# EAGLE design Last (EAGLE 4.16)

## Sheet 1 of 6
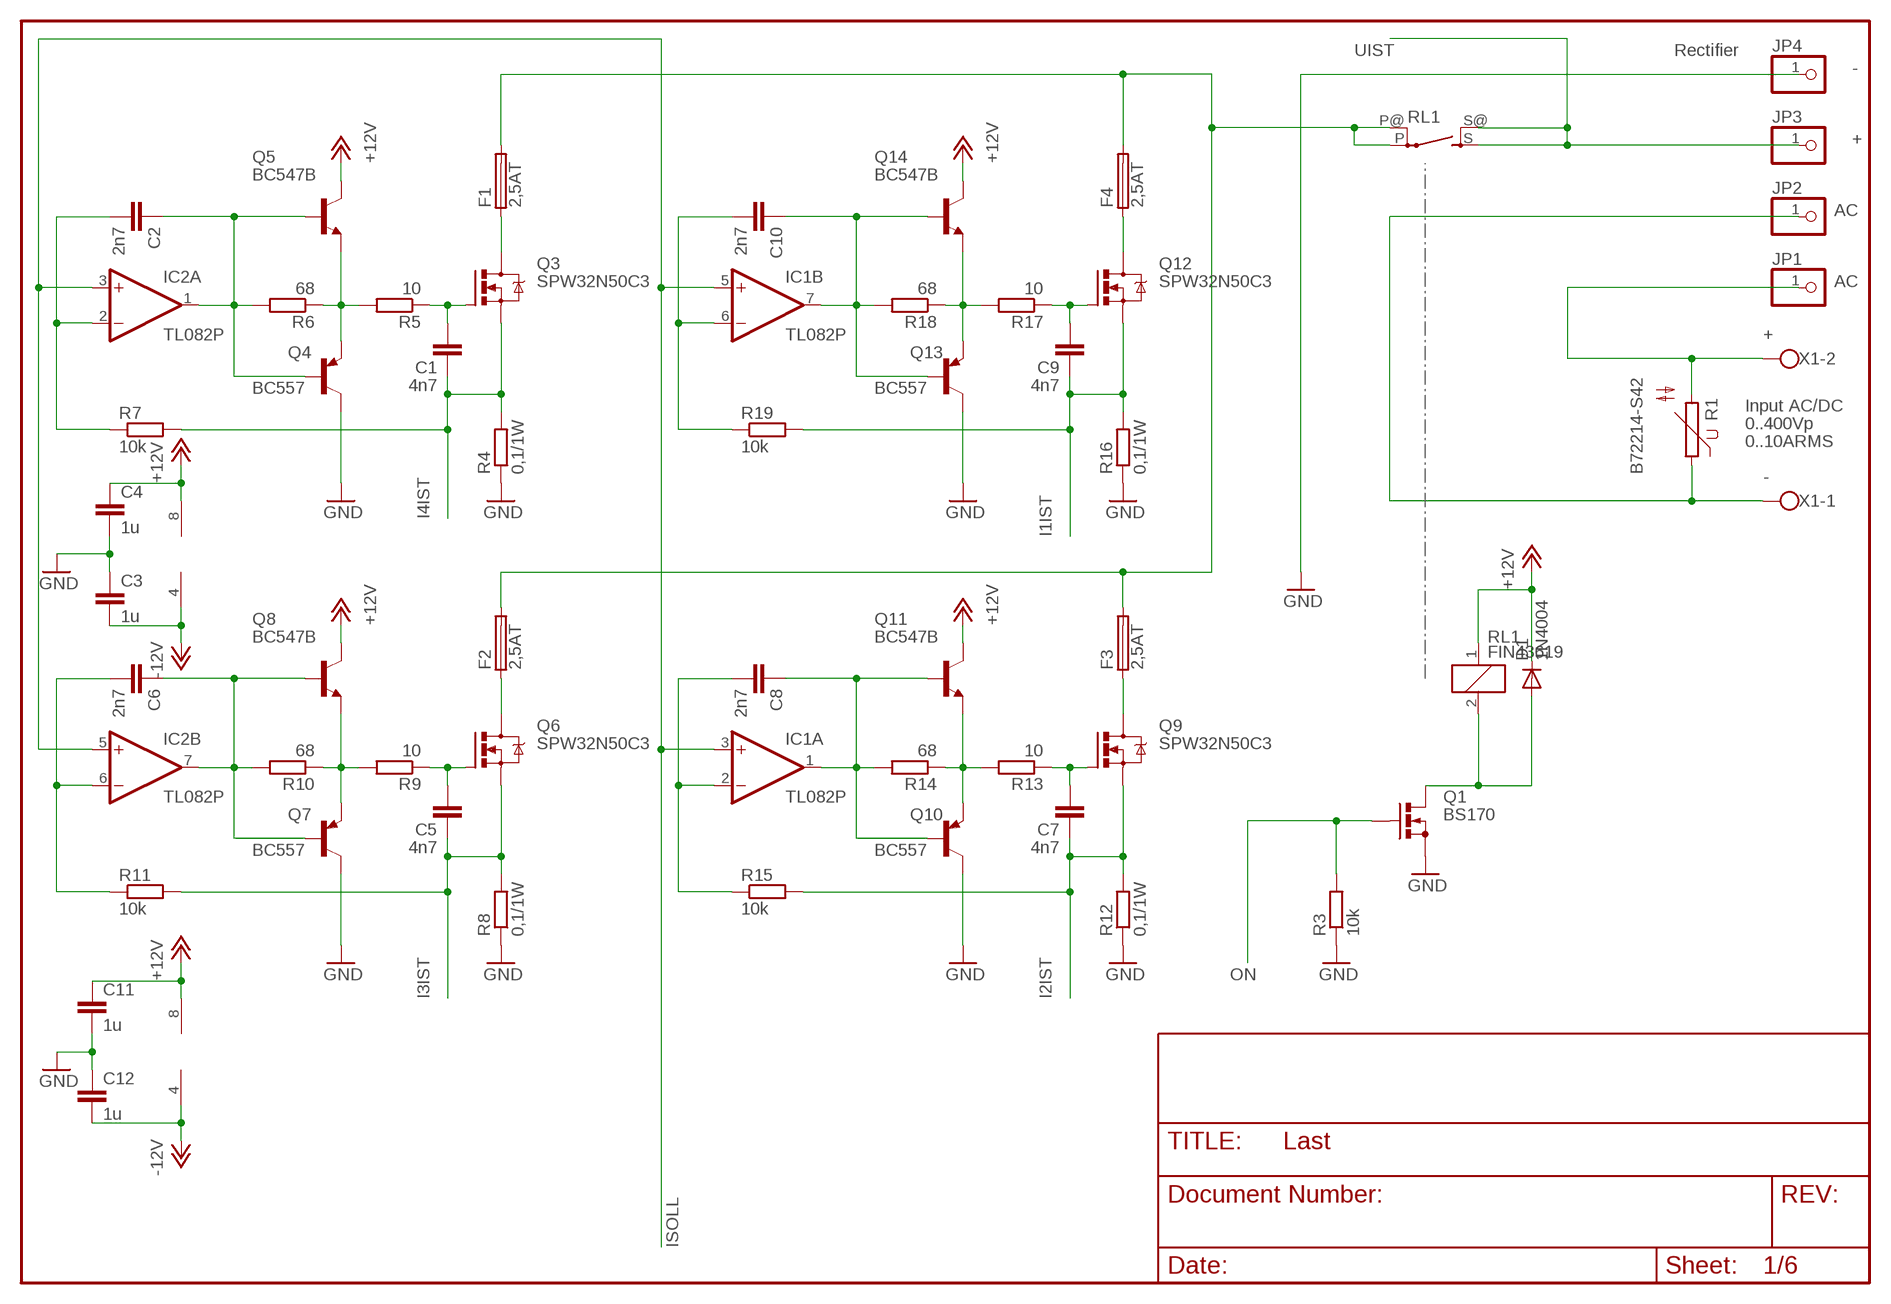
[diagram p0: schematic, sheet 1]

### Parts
C1  4n7  C-EU025-025X050  [C025-025X050]
C2  2n7  C-EU025-025X050  [C025-025X050]
C3  1u  C-EUC1210  [C1210]
C4  1u  C-EUC1210  [C1210]
C5  4n7  C-EU025-025X050  [C025-025X050]
C6  2n7  C-EU025-025X050  [C025-025X050]
C7  4n7  C-EU025-025X050  [C025-025X050]
C8  2n7  C-EU025-025X050  [C025-025X050]
C9  4n7  C-EU025-025X050  [C025-025X050]
C10  2n7  C-EU025-025X050  [C025-025X050]
C11  1u  C-EUC1210  [C1210]
C12  1u  C-EUC1210  [C1210]
D1  1N4004  [DO41-10]
F1  2,5AT  SH22,5  [SH22,5]
F2  2,5AT  SH22,5  [SH22,5]
F3  2,5AT  SH22,5  [SH22,5]
F4  2,5AT  SH22,5  [SH22,5]
IC1  TL082P  [DIL08]
IC2  TL082P  [DIL08]
JP1  PINHD-1X1  [1X01]
JP2  PINHD-1X1  [1X01]
JP3  PINHD-1X1  [1X01]
JP4  PINHD-1X1  [1X01]
Q1  BS170  [SOT54E]
Q3  SPW32N50C3  IRFPC40  [TO247BV]
Q4  BC557  [TO92]
Q5  BC547B  [TO92]
Q6  SPW32N50C3  IRFPC40  [TO247BV]
Q7  BC557  [TO92]
Q8  BC547B  [TO92]
Q9  SPW32N50C3  IRFPC40  [TO247BV]
Q10  BC557  [TO92]
Q11  BC547B  [TO92]
Q12  SPW32N50C3  IRFPC40  [TO247BV]
Q13  BC557  [TO92]
Q14  BC547B  [TO92]
R1  B72214-S42  S10K420  [S10K420]
R3  10k  R-EU_0207/10  [0207/10]
R4  0,1/1W  R-EU_0207/15  [0207/15]
R5  10  R-EU_0207/10  [0207/10]
R6  68  R-EU_0207/10  [0207/10]
R7  10k  R-EU_0207/10  [0207/10]
R8  0,1/1W  R-EU_0207/15  [0207/15]
R9  10  R-EU_0207/10  [0207/10]
R10  68  R-EU_0207/10  [0207/10]
R11  10k  R-EU_0207/10  [0207/10]
R12  0,1/1W  R-EU_0207/15  [0207/15]
R13  10  R-EU_0207/10  [0207/10]
R14  68  R-EU_0207/10  [0207/10]
R15  10k  R-EU_0207/10  [0207/10]
R16  0,1/1W  R-EU_0207/15  [0207/15]
R17  10  R-EU_0207/10  [0207/10]
R18  68  R-EU_0207/10  [0207/10]
R19  10k  R-EU_0207/10  [0207/10]
RL1  FIN43619  [FIN43619]
X1  W237-102  [W237-102]

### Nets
+12V: C4.1 C11.1 D1.C IC1.8(P:V+) IC2.8(P:V+) Q5.3(C) Q8.3(C) Q11.3(C) Q14.3(C) RL1.1 ; also sheet 2,3,4,6
-12V: C3.2 C12.2 IC1.4(P:V-) IC2.4(P:V-) ; also sheet 2,3,6
GND: C3.1 C4.2 C11.2 C12.1 JP4.1 Q1.S Q4.3(C) Q7.3(C) Q10.3(C) Q13.3(C) R3.1 R4.1 R8.1 R12.1 R16.1 ; also sheet 2,3,4,5,6
I1IST: C9.1 Q12.S R16.2 R19.2 ; also sheet 3
I2IST: C7.1 Q9.S R12.2 R15.2 ; also sheet 3
I3IST: C5.1 Q6.S R8.2 R11.2 ; also sheet 3
I4IST: C1.1 Q3.S R4.2 R7.2 ; also sheet 3
ISOLL: IC1.3(A:+IN) IC1.5(B:+IN) IC2.3(A:+IN) IC2.5(B:+IN) ; also sheet 2
N$1: JP2.1 R1.1 X1.1
N$2: JP1.1 R1.2 X1.2
N$4: D1.A Q1.D RL1.2
N$8: F1.1 Q3.D
N$11: C1.2 Q3.G R5.1
N$12: Q4.1(E) Q5.1(E) R5.2 R6.1
N$13: C2.1 IC2.1(A:OUT) Q4.2(B) Q5.2(B) R6.2
N$15: C2.2 IC2.2(A:-IN) R7.1
N$16: F2.1 Q6.D
N$18: C5.2 Q6.G R9.1
N$19: Q7.1(E) Q8.1(E) R9.2 R10.1
N$20: C6.1 IC2.7(B:OUT) Q7.2(B) Q8.2(B) R10.2
N$21: C6.2 IC2.6(B:-IN) R11.1
N$22: F3.1 Q9.D
N$24: C7.2 Q9.G R13.1
N$25: Q10.1(E) Q11.1(E) R13.2 R14.1
N$26: C8.1 IC1.1(A:OUT) Q10.2(B) Q11.2(B) R14.2
N$27: C8.2 IC1.2(A:-IN) R15.1
N$28: F4.1 Q12.D
N$30: C9.2 Q12.G R17.1
N$31: Q13.1(E) Q14.1(E) R17.2 R18.1
N$32: C10.1 IC1.7(B:OUT) Q13.2(B) Q14.2(B) R18.2
N$33: C10.2 IC1.6(B:-IN) R19.1
ON: Q1.G R3.2 ; also sheet 4
U+: F1.2 F2.2 F3.2 F4.2 RL1.P RL1.P@(P)
UIST: JP3.1 RL1.S RL1.S@(S) ; also sheet 2

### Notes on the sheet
- Rectifier
- -
- +
- AC
- AC
- +
- Input AC/DC
- 0..400Vp
- 0..10ARMS
- -

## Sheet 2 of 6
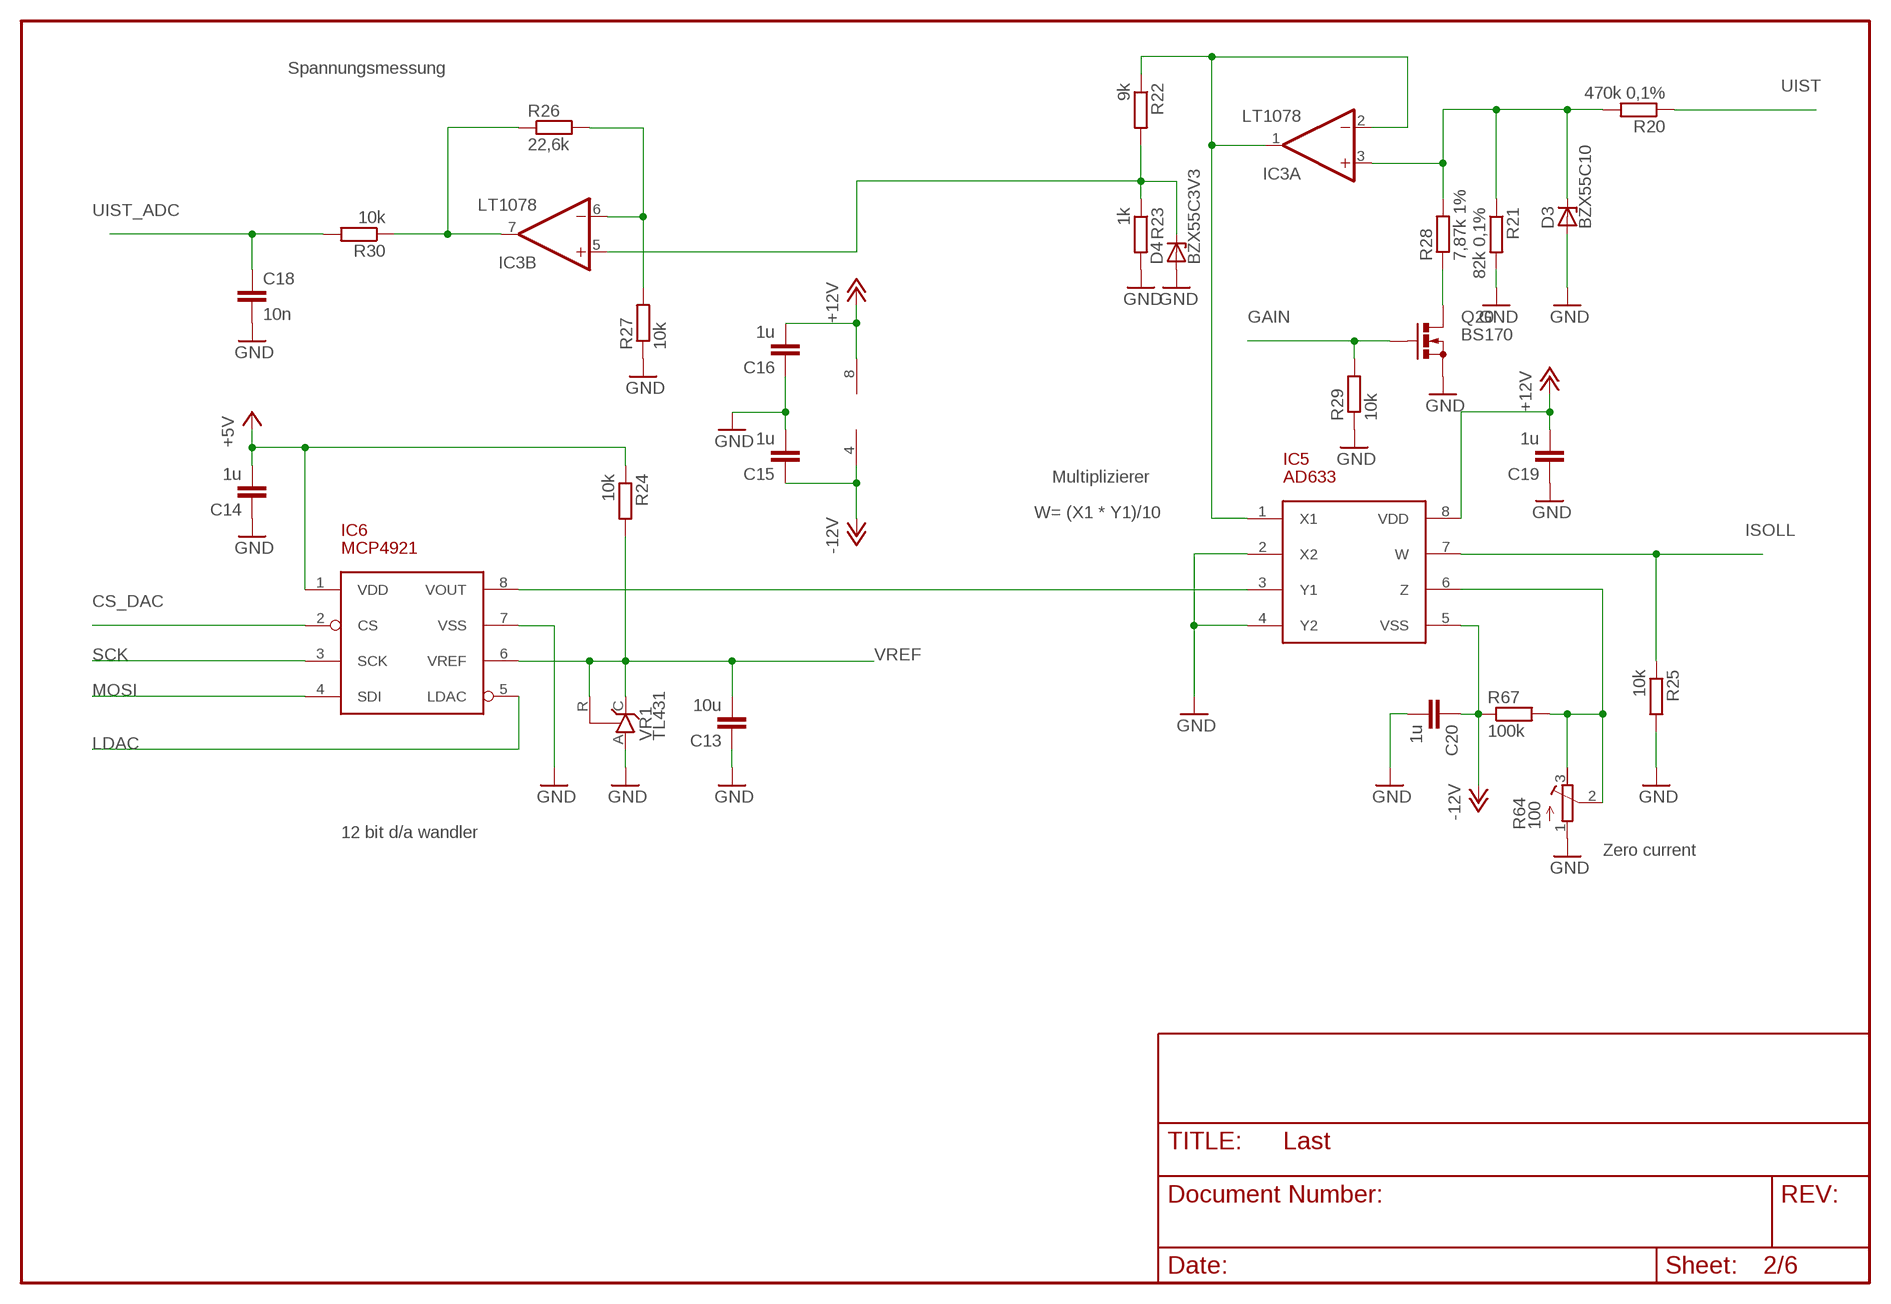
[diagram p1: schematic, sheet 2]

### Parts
C13  10u  C-EUC1210  [C1210]
C14  1u  C-EUC1210  [C1210]
C15  1u  C-EUC1210  [C1210]
C16  1u  C-EUC1210  [C1210]
C18  10n  C-EU025-025X050  [C025-025X050]
C19  1u  C-EUC1210  [C1210]
C20  1u  C-EUC1210  [C1210]
D3  BZX55C10  ZPD  [DO35Z10]
D4  BZX55C3V3  ZPD  [DO35Z10]
IC3  LT1078  TL082P  [DIL08]
IC5  AD633  [DIL08]
IC6  MCP4921  [DIL8]
Q20  BS170  [SOT54E]
R20  470k 0,1%  R-EU_0207/10  [0207/10]
R21  82k 0,1%  R-EU_0207/10  [0207/10]
R22  9k  R-EU_0207/10  [0207/10]
R23  1k  R-EU_0207/10  [0207/10]
R24  10k  R-EU_0207/10  [0207/10]
R25  10k  R-EU_0207/10  [0207/10]
R26  22,6k  R-EU_0207/10  [0207/10]
R27  10k  R-EU_0207/10  [0207/10]
R28  7,87k 1%  R-EU_0207/10  [0207/10]
R29  10k  R-EU_0207/10  [0207/10]
R30  10k  R-EU_0207/10  [0207/10]
R64  100  R-TRIMM64W  [RTRIM64W]
R67  100k  R-EU_0207/10  [0207/10]
VR1  TL431  TL431CLP  [TO92-CLP]

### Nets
+5V: C14.2 IC6.1(VDD) R24.1 ; also sheet 4,5,6
+12V: C16.2 C19.2 IC3.8(P:V+) IC5.8(VDD) ; also sheet 1,3,4,6
-12V: C15.1 C20.1 IC3.4(P:V-) IC5.5(VSS) R67.1 ; also sheet 1,3,6
CS_DAC: IC6.2(CS) ; also sheet 4
GAIN: Q20.G R29.2 ; also sheet 4
GND: C13.1 C14.1 C15.2 C16.1 C18.2 C19.1 C20.2 D3.A D4.A IC5.2(X2) IC5.4(Y2) IC6.7(VSS) Q20.S R21.2 R23.2 R25.2 R27.1 R29.1 R64.1(E) VR1.A ; also sheet 1,3,4,5,6
ISOLL: IC5.7(W) R25.1 ; also sheet 1
LDAC: IC6.5(LDAC) ; also sheet 4
MOSI: IC6.4(SDI) ; also sheet 4
N$6: IC5.6(Z) R64.2(S) R64.3(A) R67.2
N$10: D3.C IC3.3(A:+IN) R20.2 R21.1 R28.2
N$14: Q20.D R28.1
N$17: IC3.1(A:OUT) IC3.2(A:-IN) IC5.1(X1) R22.1
N$23: D4.C IC3.5(B:+IN) R22.2 R23.1
N$29: IC5.3(Y1) IC6.8(VOUT)
N$37: IC3.6(B:-IN) R26.2 R27.2
N$38: IC3.7(B:OUT) R26.1 R30.1
SCK: IC6.3(SCK) ; also sheet 4
UIST: R20.1 ; also sheet 1
UIST_ADC: C18.1 R30.2 ; also sheet 4
VREF: C13.2 IC6.6(VREF) R24.2 VR1.C VR1.R ; also sheet 3

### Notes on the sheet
- Spannungsmessung
- Multiplizierer
- W= (X1 * Y1)/10
- 12 bit d/a wandler
- Zero current

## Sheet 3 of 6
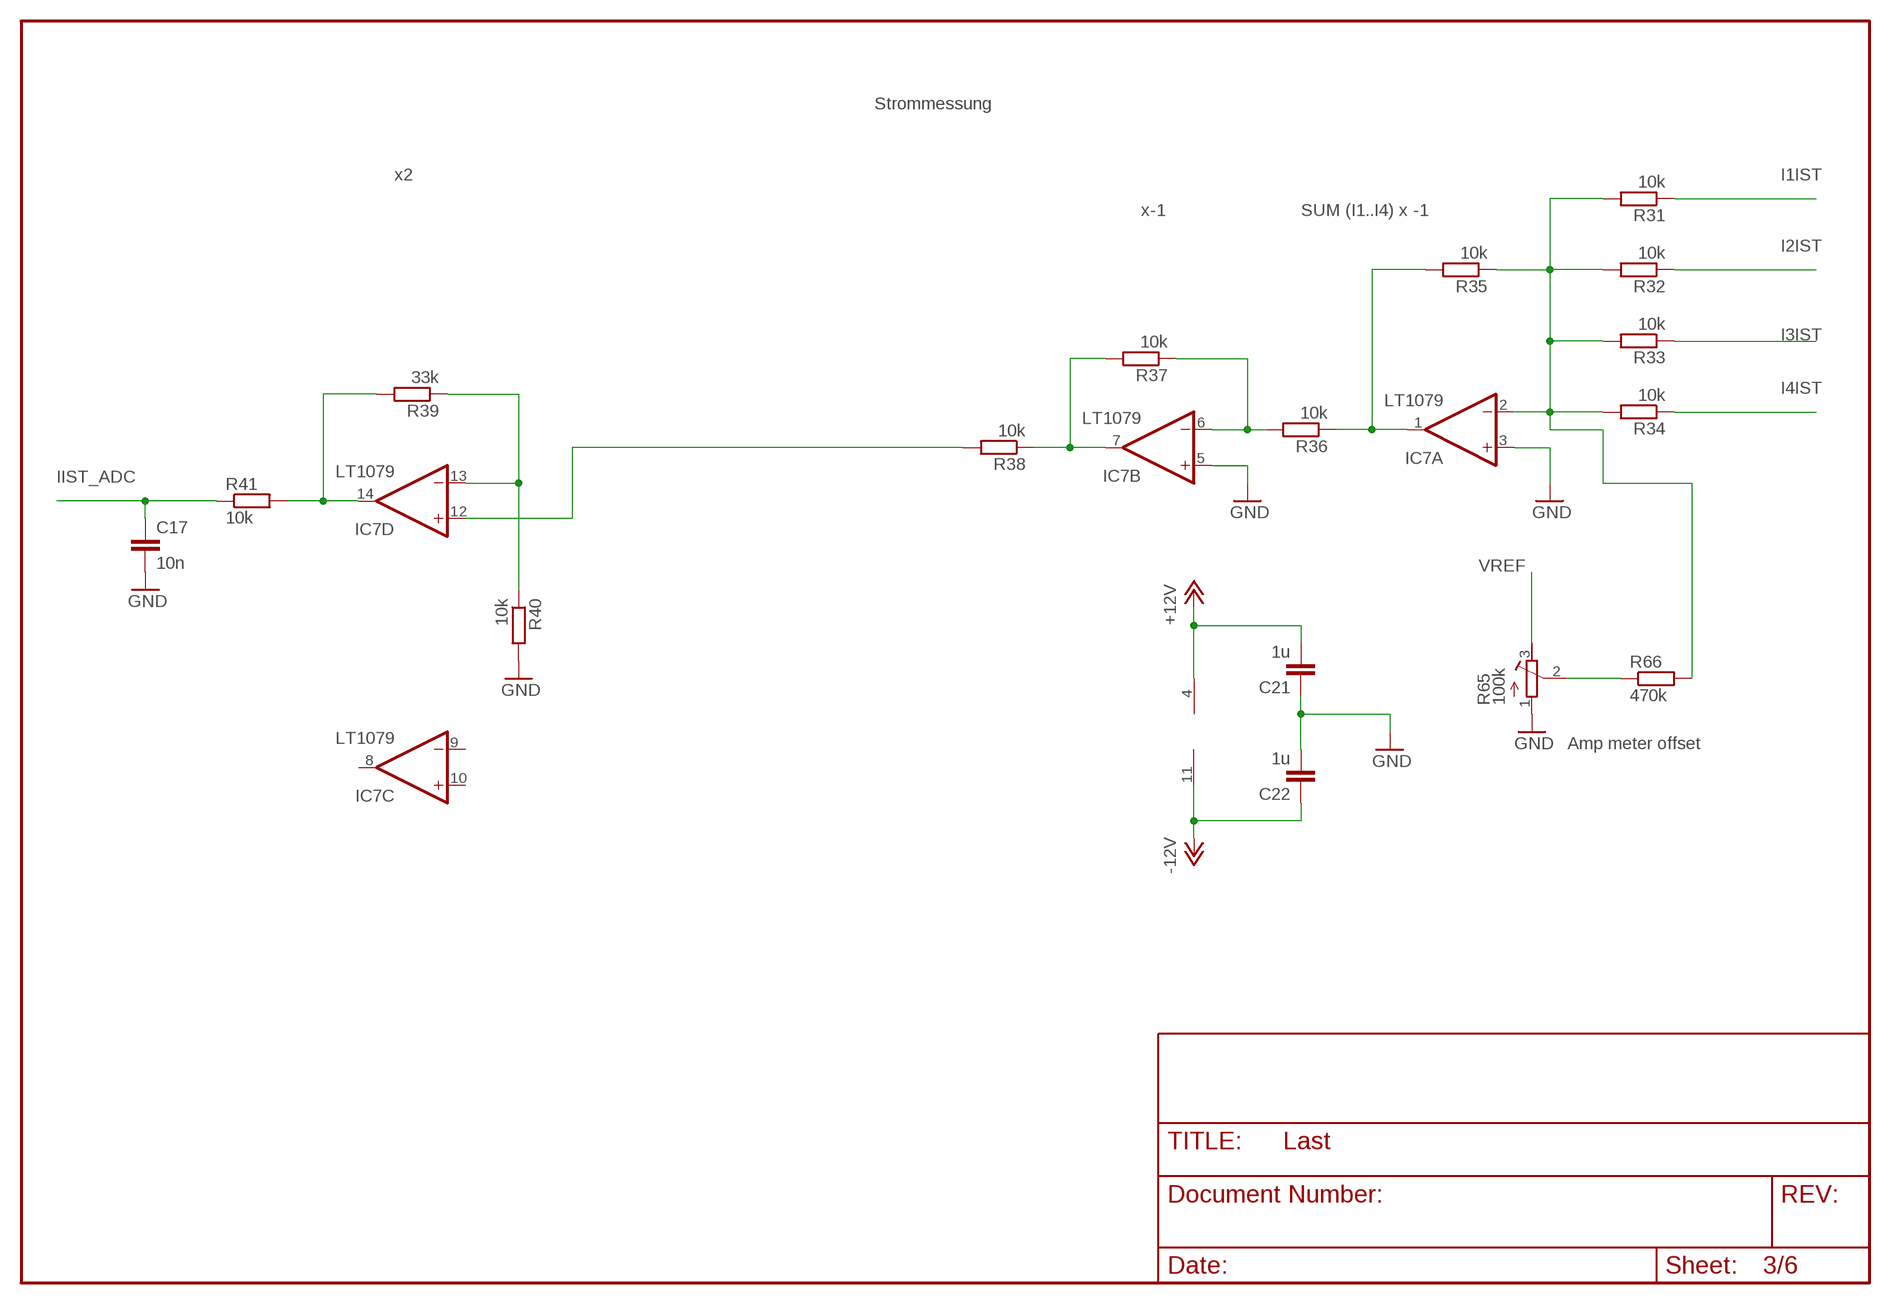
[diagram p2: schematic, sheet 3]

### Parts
C17  10n  C-EU025-025X050  [C025-025X050]
C21  1u  C-EUC1210  [C1210]
C22  1u  C-EUC1210  [C1210]
IC7  LT1079  TL084P  [DIL14]
R31  10k  R-EU_0207/10  [0207/10]
R32  10k  R-EU_0207/10  [0207/10]
R33  10k  R-EU_0207/10  [0207/10]
R34  10k  R-EU_0207/10  [0207/10]
R35  10k  R-EU_0207/10  [0207/10]
R36  10k  R-EU_0207/10  [0207/10]
R37  10k  R-EU_0207/10  [0207/10]
R38  10k  R-EU_0207/10  [0207/10]
R39  33k  R-EU_0207/10  [0207/10]
R40  10k  R-EU_0207/10  [0207/10]
R41  10k  R-EU_0207/10  [0207/10]
R65  100k  R-TRIMM64W  [RTRIM64W]
R66  470k  R-EU_0207/10  [0207/10]

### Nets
+12V: C21.2 IC7.4(P:V+) ; also sheet 1,2,4,6
-12V: C22.1 IC7.11(P:V-) ; also sheet 1,2,6
GND: C17.2 C21.1 C22.2 IC7.3(A:+IN) IC7.5(B:+IN) R40.2 R65.1(E) ; also sheet 1,2,4,5,6
I1IST: R31.1 ; also sheet 1
I2IST: R32.1 ; also sheet 1
I3IST: R33.1 ; also sheet 1
I4IST: R34.1 ; also sheet 1
IIST_ADC: C17.1 R41.1 ; also sheet 4
N$34: IC7.2(A:-IN) R31.2 R32.2 R33.2 R34.2 R35.1 R66.2
N$35: R65.2(S) R66.1
N$36: IC7.1(A:OUT) R35.2 R36.1
N$39: IC7.6(B:-IN) R36.2 R37.1
N$41: IC7.7(B:OUT) R37.2 R38.1
N$42: IC7.12(D:+IN) R38.2
N$44: IC7.13(D:-IN) R39.1 R40.1
N$45: IC7.14(D:OUT) R39.2 R41.2
VREF: R65.3(A) ; also sheet 2
Unconnected: IC7.8(C:OUT) IC7.9(C:-IN) IC7.10(C:+IN)

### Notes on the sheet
- Strommessung
- x2
- x-1 | SUM (I1..I4) x -1
- Amp meter offset

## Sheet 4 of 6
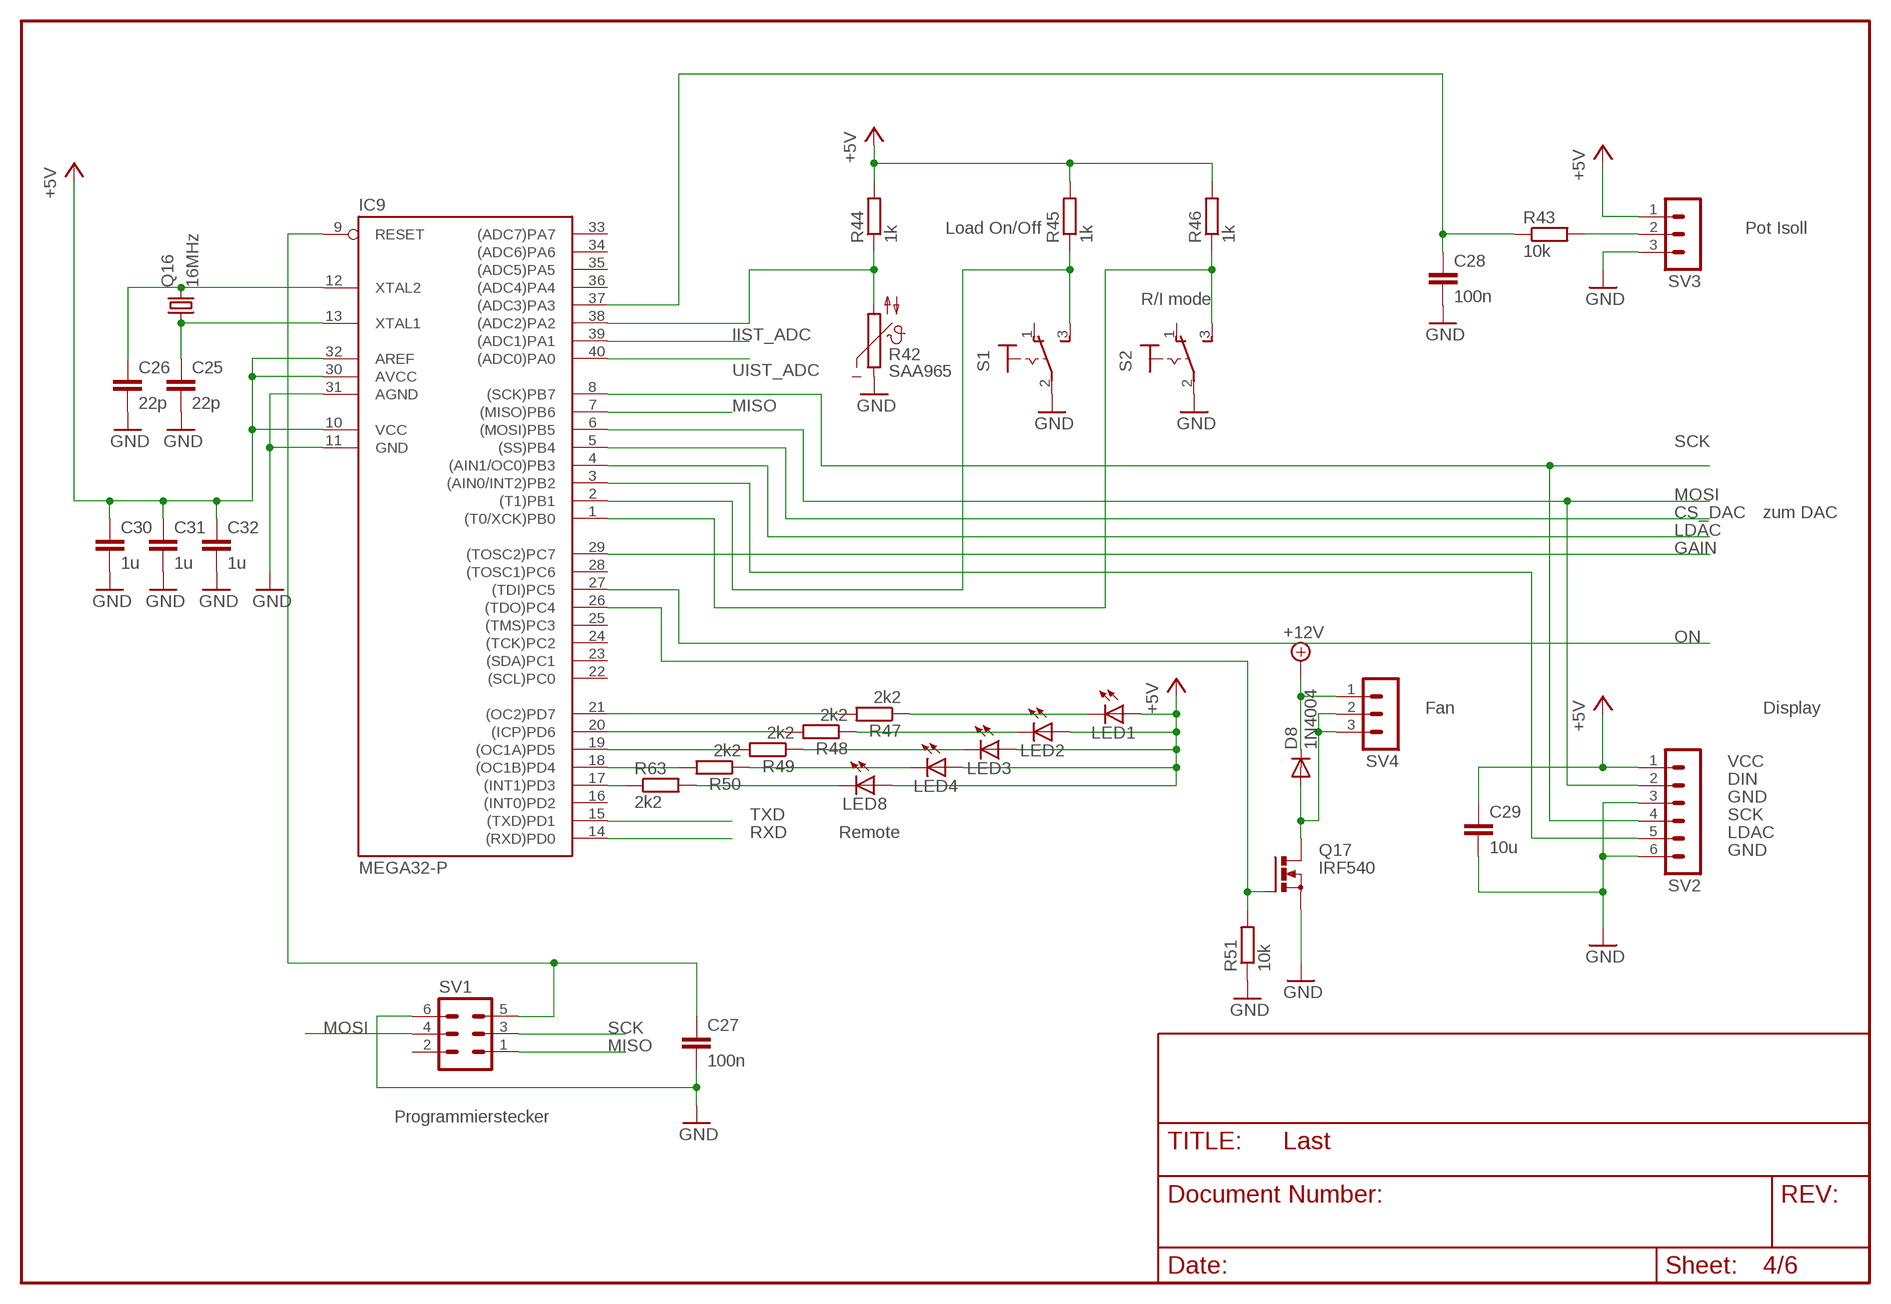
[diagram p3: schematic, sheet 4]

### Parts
C25  22p  C-EU025-025X050  [C025-025X050]
C26  22p  C-EU025-025X050  [C025-025X050]
C27  100n  C-EU025-025X050  [C025-025X050]
C28  100n  C-EU025-025X050  [C025-025X050]
C29  10u  C-EUC1210  [C1210]
C30  1u  C-EUC1210  [C1210]
C31  1u  C-EUC1210  [C1210]
C32  1u  C-EUC1210  [C1210]
D8  1N4004  [DO41-10]
IC9  MEGA32-P  [DIL40]
LED1  LED3MM  [LED3MM]
LED2  LED3MM  [LED3MM]
LED3  LED3MM  [LED3MM]
LED4  LED3MM  [LED3MM]
LED8  LED3MM  [LED3MM]
Q16  16MHz  CRYTALHC49S  [HC49/S]
Q17  IRF540  BUZ11BV  [TO220BV]
R42  SAA965  NTC640  [P640]
R43  10k  R-EU_0207/10  [0207/10]
R44  1k  R-EU_0207/10  [0207/10]
R45  1k  R-EU_0207/10  [0207/10]
R46  1k  R-EU_0207/10  [0207/10]
R47  2k2  R-EU_0207/10  [0207/10]
R48  2k2  R-EU_0207/10  [0207/10]
R49  2k2  R-EU_0207/10  [0207/10]
R50  2k2  R-EU_0207/10  [0207/10]
R51  10k  R-EU_0207/10  [0207/10]
R63  2k2  R-EU_0207/10  [0207/10]
S1  320-916  [320-916]
S2  320-916  [320-916]
SV1  MA03-2  [MA03-2]
SV2  MA06-1  [MA06-1]
SV3  MA03-1  [MA03-1]
SV4  MA03-1  [MA03-1]

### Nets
+5V: C29.1 C30.1 C31.1 C32.1 IC9.10(VCC) IC9.30(AVCC) IC9.32(AREF) LED1.A LED2.A LED3.A LED4.A LED8.A R44.2 R45.2 R46.2 SV2.1 SV3.1 ; also sheet 2,5,6
+12V: D8.C SV4.1 ; also sheet 1,2,3,6
CS_DAC: IC9.5((SS)PB4) ; also sheet 2
GAIN: IC9.29((TOSC2)PC7) ; also sheet 2
GND: C25.2 C26.2 C27.2 C28.2 C29.2 C30.2 C31.2 C32.2 IC9.11(GND) IC9.31(AGND) Q17.S R42.1 R51.1 S1.2(P) S2.2(P) SV1.6 SV2.3 SV2.6 SV3.3 ; also sheet 1,2,3,5,6
IIST_ADC: IC9.39((ADC1)PA1) ; also sheet 3
LDAC: IC9.4((AIN1/OC0)PB3) ; also sheet 2
MISO: IC9.7((MISO)PB6) SV1.1
MOSI: IC9.6((MOSI)PB5) SV1.4 SV2.2 ; also sheet 2
N$7: IC9.38((ADC2)PA2) R42.2 R44.1
N$40: IC9.2((T1)PB1) R45.1 S1.3(S)
N$46: R43.2 SV3.2
N$47: C28.1 IC9.37((ADC3)PA3) R43.1
N$48: IC9.1((T0/XCK)PB0) R46.1 S2.3(S)
N$49: C26.1 IC9.12(XTAL2) Q16.2
N$50: C25.1 IC9.13(XTAL1) Q16.1
N$51: D8.A Q17.D SV4.2 SV4.3
N$52: C27.1 IC9.9(RESET) SV1.5
N$53: IC9.3((AIN0/INT2)PB2) SV2.5
N$54: IC9.17((INT1)PD3) R63.1
N$55: IC9.26((TDO)PC4) Q17.G R51.2
N$56: LED1.K(C) R47.1
N$57: IC9.21((OC2)PD7) R47.2
N$58: IC9.20((ICP)PD6) R48.2
N$59: LED2.K(C) R48.1
N$60: IC9.19((OC1A)PD5) R49.2
N$61: LED3.K(C) R49.1
N$62: IC9.18((OC1B)PD4) R50.2
N$63: LED4.K(C) R50.1
N$85: LED8.K(C) R63.2
ON: IC9.27((TDI)PC5) ; also sheet 1
RXD: IC9.14((RXD)PD0) ; also sheet 5
SCK: IC9.8((SCK)PB7) SV1.3 SV2.4 ; also sheet 2
TXD: IC9.15((TXD)PD1) ; also sheet 5
UIST_ADC: IC9.40((ADC0)PA0) ; also sheet 2
Unconnected: IC9.16((INT0)PD2) IC9.22((SCL)PC0) IC9.23((SDA)PC1) IC9.24((TCK)PC2) IC9.25((TMS)PC3) IC9.28((TOSC1)PC6) IC9.33((ADC7)PA7) IC9.34((ADC6)PA6) IC9.35((ADC5)PA5) IC9.36((ADC4)PA4) S1.1(O) S2.1(O) SV1.2

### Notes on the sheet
- Load On/Off | Pot Isoll
- R/I mode
- zum DAC
- Fan | Display
- VCC
- DIN
- GND
- SCK
- Remote | LDAC
- GND
- Programmierstecker

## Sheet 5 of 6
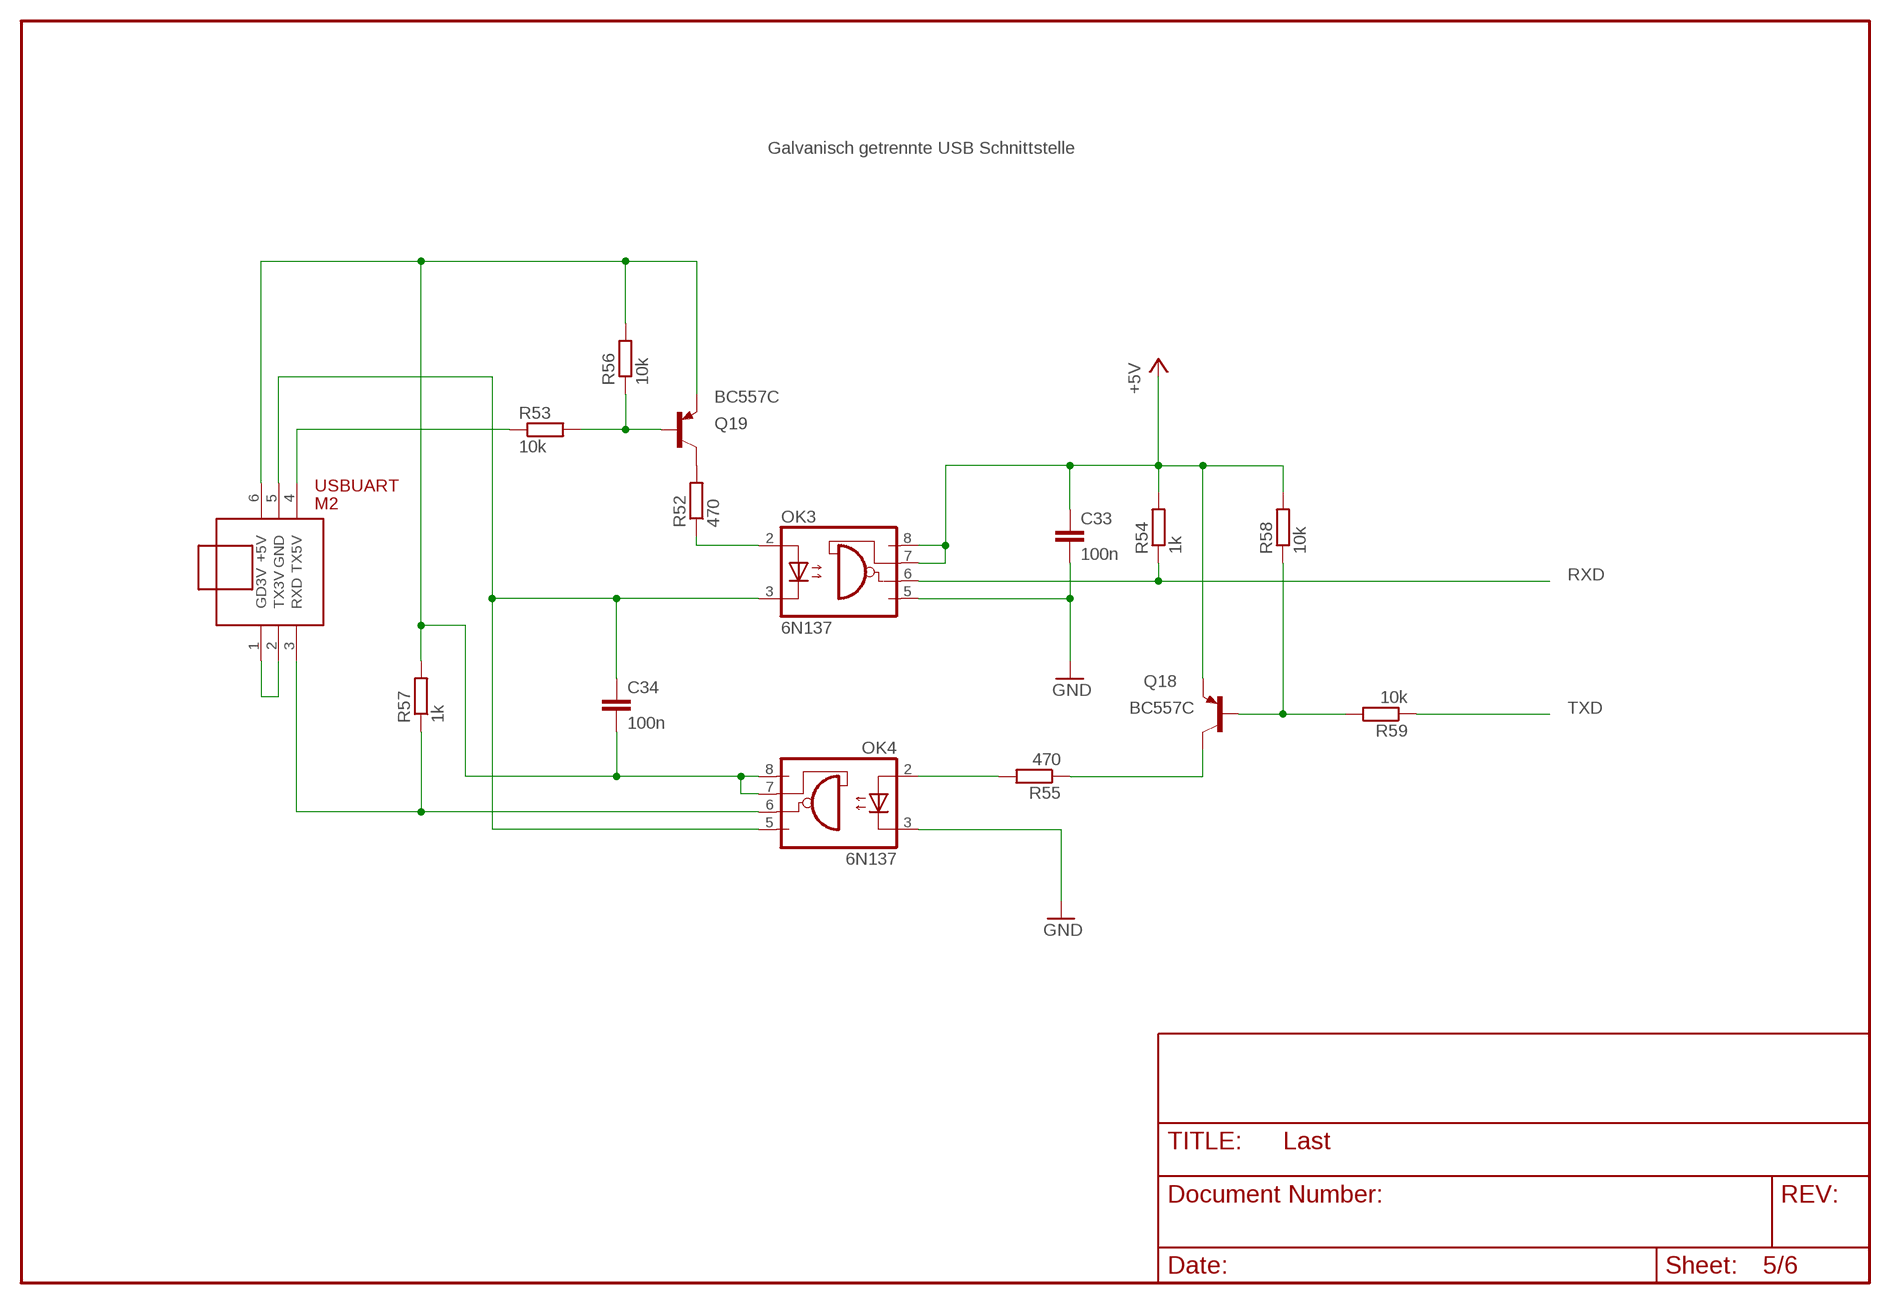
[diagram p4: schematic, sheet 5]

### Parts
C33  100n  C-EU025-025X050  [C025-025X050]
C34  100n  C-EU025-025X050  [C025-025X050]
M2  USBUART  [USBUART]
OK3  6N137  [DIL08]
OK4  6N137  [DIL08]
Q18  BC557C  [TO92-EBC]
Q19  BC557C  [TO92-EBC]
R52  470  R-EU_0207/10  [0207/10]
R53  10k  R-EU_0207/10  [0207/10]
R54  1k  R-EU_0207/10  [0207/10]
R55  470  R-EU_0207/10  [0207/10]
R56  10k  R-EU_0207/10  [0207/10]
R57  1k  R-EU_0207/10  [0207/10]
R58  10k  R-EU_0207/10  [0207/10]
R59  10k  R-EU_0207/10  [0207/10]

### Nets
+5V: C33.1 OK3.7(VE) OK3.8(VCC) Q18.E R54.2 R58.2 ; also sheet 2,4,6
GND: C33.2 OK3.5(GND) OK4.3(C) ; also sheet 1,2,3,4,6
N$64: Q19.C R52.2
N$65: C34.2 M2.6(+5V) OK4.7(VE) OK4.8(VCC) Q19.E R56.2 R57.2
N$66: OK3.2(A) R52.1
N$67: M2.3(RXD) OK4.6(VO) R57.1
N$68: Q19.B R53.2 R56.1
N$69: M2.4(TX5V) R53.1
N$70: M2.1(GD3V) M2.2(TX3V)
N$71: C34.1 M2.5(GND) OK3.3(C) OK4.5(GND)
N$72: Q18.B R58.1 R59.2
N$73: OK4.2(A) R55.2
N$74: Q18.C R55.1
RXD: OK3.6(VO) R54.1 ; also sheet 4
TXD: R59.1 ; also sheet 4

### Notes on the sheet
- Galvanisch getrennte USB Schnittstelle

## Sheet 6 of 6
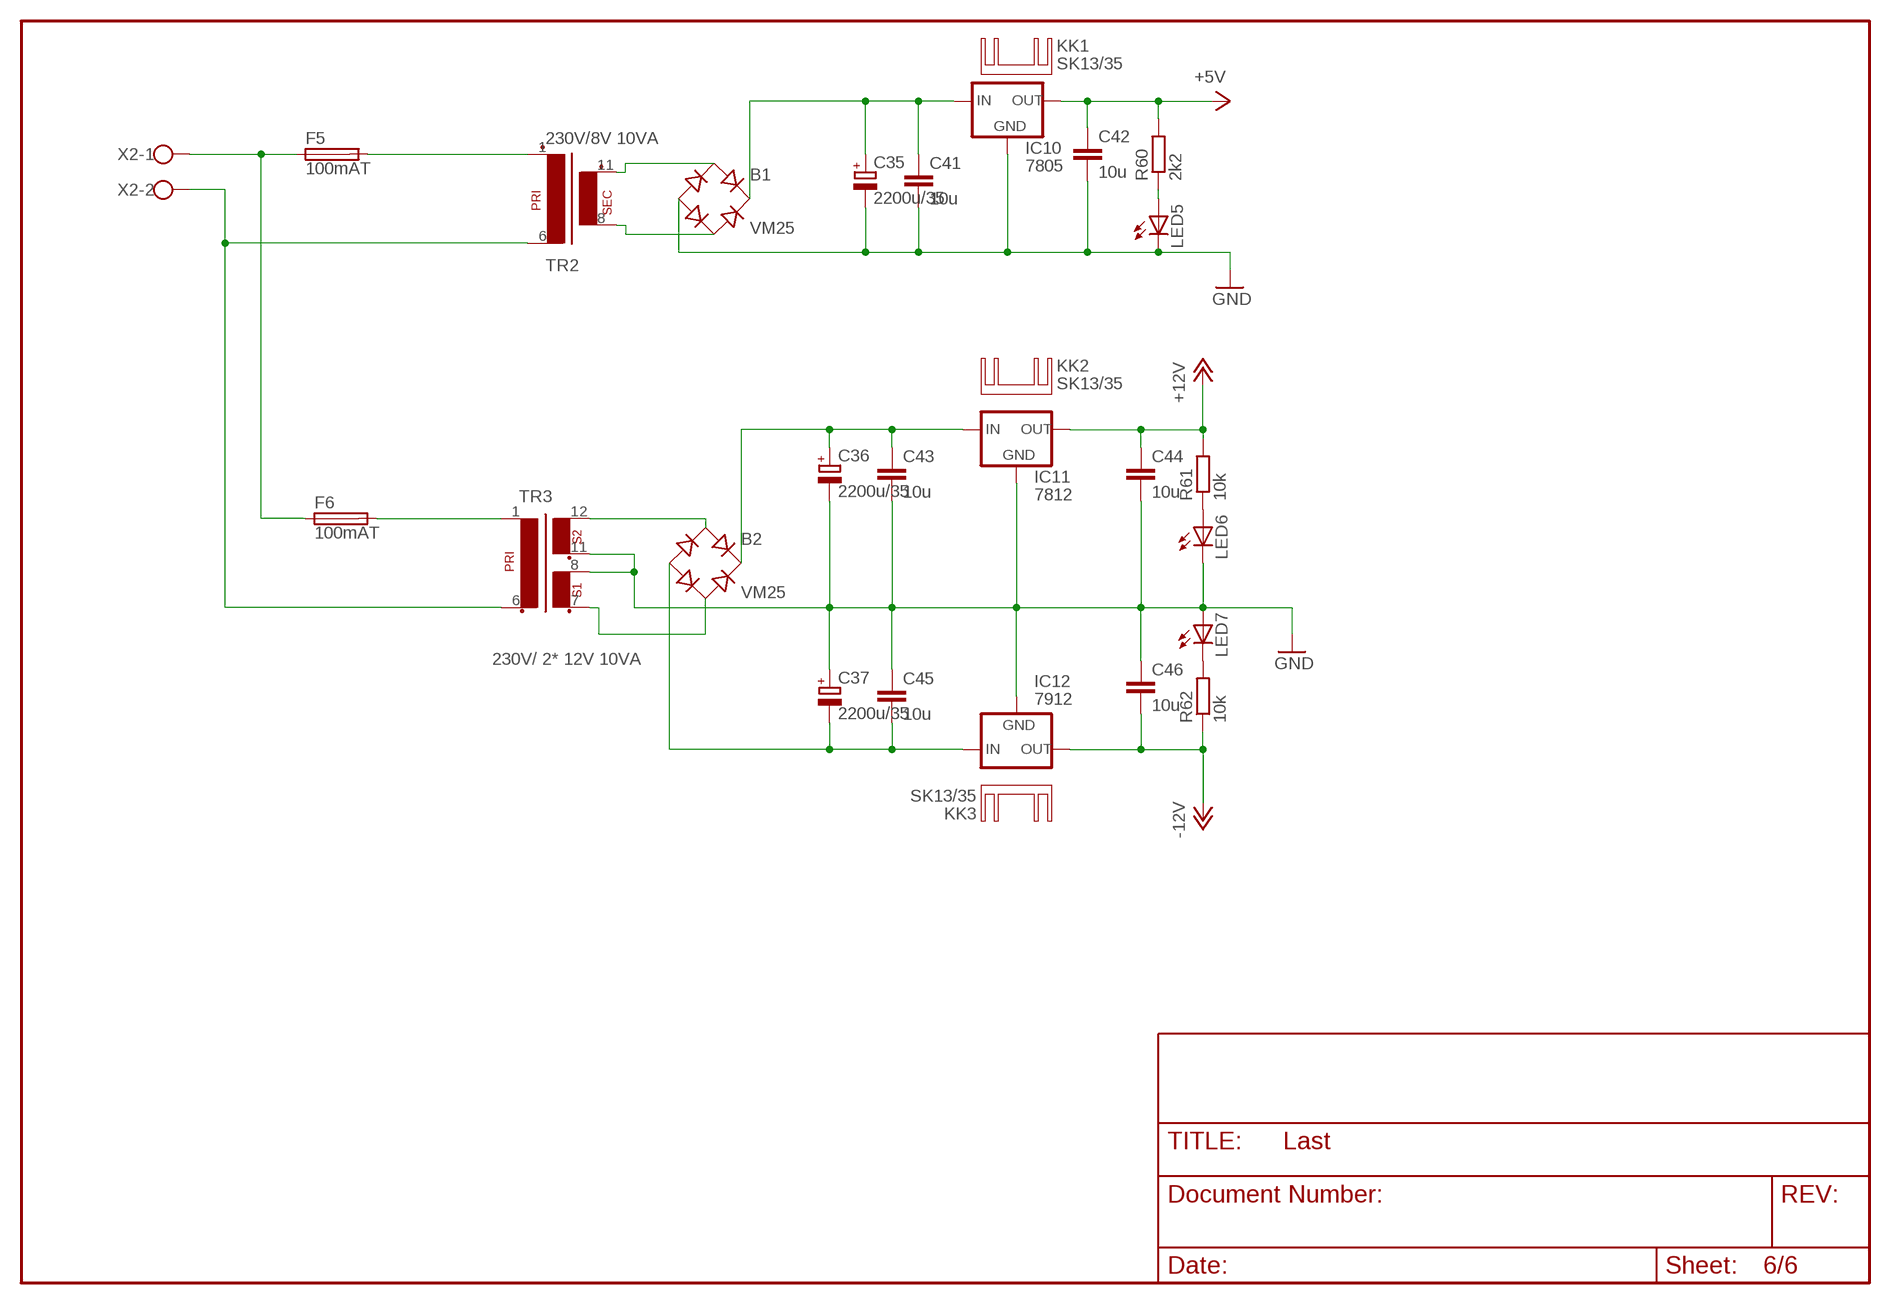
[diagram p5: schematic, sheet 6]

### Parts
B1  VM25  B-DIL  [B-DIL]
B2  VM25  B-DIL  [B-DIL]
C35  2200u/35  CPOL-EUE7.5-16  [E7,5-16]
C36  2200u/35  CPOL-EUE7.5-16  [E7,5-16]
C37  2200u/35  CPOL-EUE7.5-16  [E7,5-16]
C41  10u  C-EUC1210  [C1210]
C42  10u  C-EUC1210  [C1210]
C43  10u  C-EUC1210  [C1210]
C44  10u  C-EUC1210  [C1210]
C45  10u  C-EUC1210  [C1210]
C46  10u  C-EUC1210  [C1210]
F5  100mAT  SH22,5  [SH22,5]
F6  100mAT  SH22,5  [SH22,5]
IC10  7805  78XXL  [78XXL]
IC11  7812  78XXL  [78XXL]
IC12  7912  79XXL  [79XXL]
KK1  SK13/35  [SK13/35]
KK2  SK13/35  [SK13/35]
KK3  SK13/35  [SK13/35]
LED5  LED3MM  [LED3MM]
LED6  LED3MM  [LED3MM]
LED7  LED3MM  [LED3MM]
R60  2k2  R-EU_0207/10  [0207/10]
R61  10k  R-EU_0207/10  [0207/10]
R62  10k  R-EU_0207/10  [0207/10]
TR2  230V/8V 10VA  EI48-1B  [EI48-1B]
TR3  230V/ 2* 12V 10VA  EI48-2B  [EI48-2B]
X2  W237-102  [W237-102]

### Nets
+5V: C42.1 IC10.OUT R60.2 ; also sheet 2,4,5
+12V: C44.1 IC11.OUT R61.2 ; also sheet 1,2,3,4
-12V: C46.2 IC12.OUT R62.1 ; also sheet 1,2,3
GND: B1.- C35.- C36.- C37.+ C41.2 C42.2 C43.2 C44.2 C45.1 C46.1 IC10.GND IC11.GND IC12.GND LED5.K(C) LED6.K(C) LED7.A TR3.8 TR3.11 ; also sheet 1,2,3,4,5
N$75: F5.1 F6.1 X2.1
N$76: F5.2 TR2.1
N$77: F6.2 TR3.1
N$78: TR2.6 TR3.6 X2.2
N$79: B1.AC1 TR2.11
N$80: B1.AC2 TR2.8
N$81: LED5.A R60.1
N$82: B1.+ C35.+ C41.1 IC10.IN
N$83: LED6.A R61.1
N$84: LED7.K(C) R62.2
N$86: B2.AC1 TR3.12
N$87: B2.AC2 TR3.7
N$88: B2.+ C36.+ C43.1 IC11.IN
N$90: B2.- C37.- C45.2 IC12.IN

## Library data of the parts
B1 B2 = rectifier:B-DIL: RECTIFIER
C1-C22 C25-C34 C41-C46 = rcl:C-EU: CAPACITOR, European symbol
C35-C37 = rcl:CPOL-EU: POLARIZED CAPACITOR, European symbol
D1 D8 = diode:1N4004: DIODE
D3 D4 = diode:ZPD: Z DIODE
F1-F6 = fuse:SH22,5: FUSE HOLDER
IC1-IC3 = linear:TL082: OP AMP
IC5 = analog-devices:AD633
IC6 = microchip:MCP4921
IC7 = linear:TL084: OP AMP
IC9 = atmel:MEGA32-P: MICROCONTROLLER 32 Kbytes FLASH 2 Kbytes SRAM 1 Kbytes EEPROM USART 8-channel 10 bit ADC Source: www.atmel.com .. doc2503.pdf
IC10 IC11 = v-reg:78XXL: VOLTAGE REGULATOR
IC12 = v-reg:79XXL: VOLTAGE REGULATOR
JP1-JP4 = pinhead:PINHD-1X1: PIN HEADER
KK1-KK3 = heatsink:SK13/35: HEATSINK
LED1-LED8 = led:LED: LED
M2 = special:USBUART
OK3 OK4 = optocoupler:6N137: MOTOROLA OPTO COUPLER
Q1 Q20 = transistor-small-signal:BS170: N-CHANNEL MOS FET
Q3 Q6 Q9 Q12 = transistor-power:IRFPC40: N-CHANNEL MOS FET
Q4 Q7 Q10 Q13 = transistor-pnp:BC557: PNP Transistor
Q5 Q8 Q11 Q14 = transistor-npn:BC547*: NPN Transistor
Q16 = crystal:CRYTAL: CRYSTAL
Q17 = transistor-power:BUZ11: N-CHANNEL MOS FET
Q18 Q19 = transistor-pnp:BC557*: PNP Transistror
R1 = varistor:S10K420: VARISTOR
R3-R41 R43-R63 R66 R67 = rcl:R-EU_: RESISTOR, European symbol
R42 = ptc-ntc:NTC640: PHILIPS NTC
R64 R65 = rcl:R-TRIMM: Trimm resistor
RL1 = relay:FIN43619
S1 S2 = switch:320-916: TOGGLE SWITCH distributor RS Components
SV1 = con-lstb:MA03-2: PIN HEADER
SV2 = con-lstb:MA06-1: PIN HEADER
SV3 SV4 = con-lstb:MA03-1: PIN HEADER
TR2 = trafo:EI48-1B: TRANSFORMER 1 primary winding, 1 secondary winding, mounting holes ERA
TR3 = trafo:EI48-2B: TRANSFORMER 1 primary winding, 2 secondary windings, mounting holes ERA
VR1 = v-reg:TL431CLP: VOLTAGE REGULATOR
X1 X2 = con-wago-500:W237-102: WAGO SCREW CLAMP

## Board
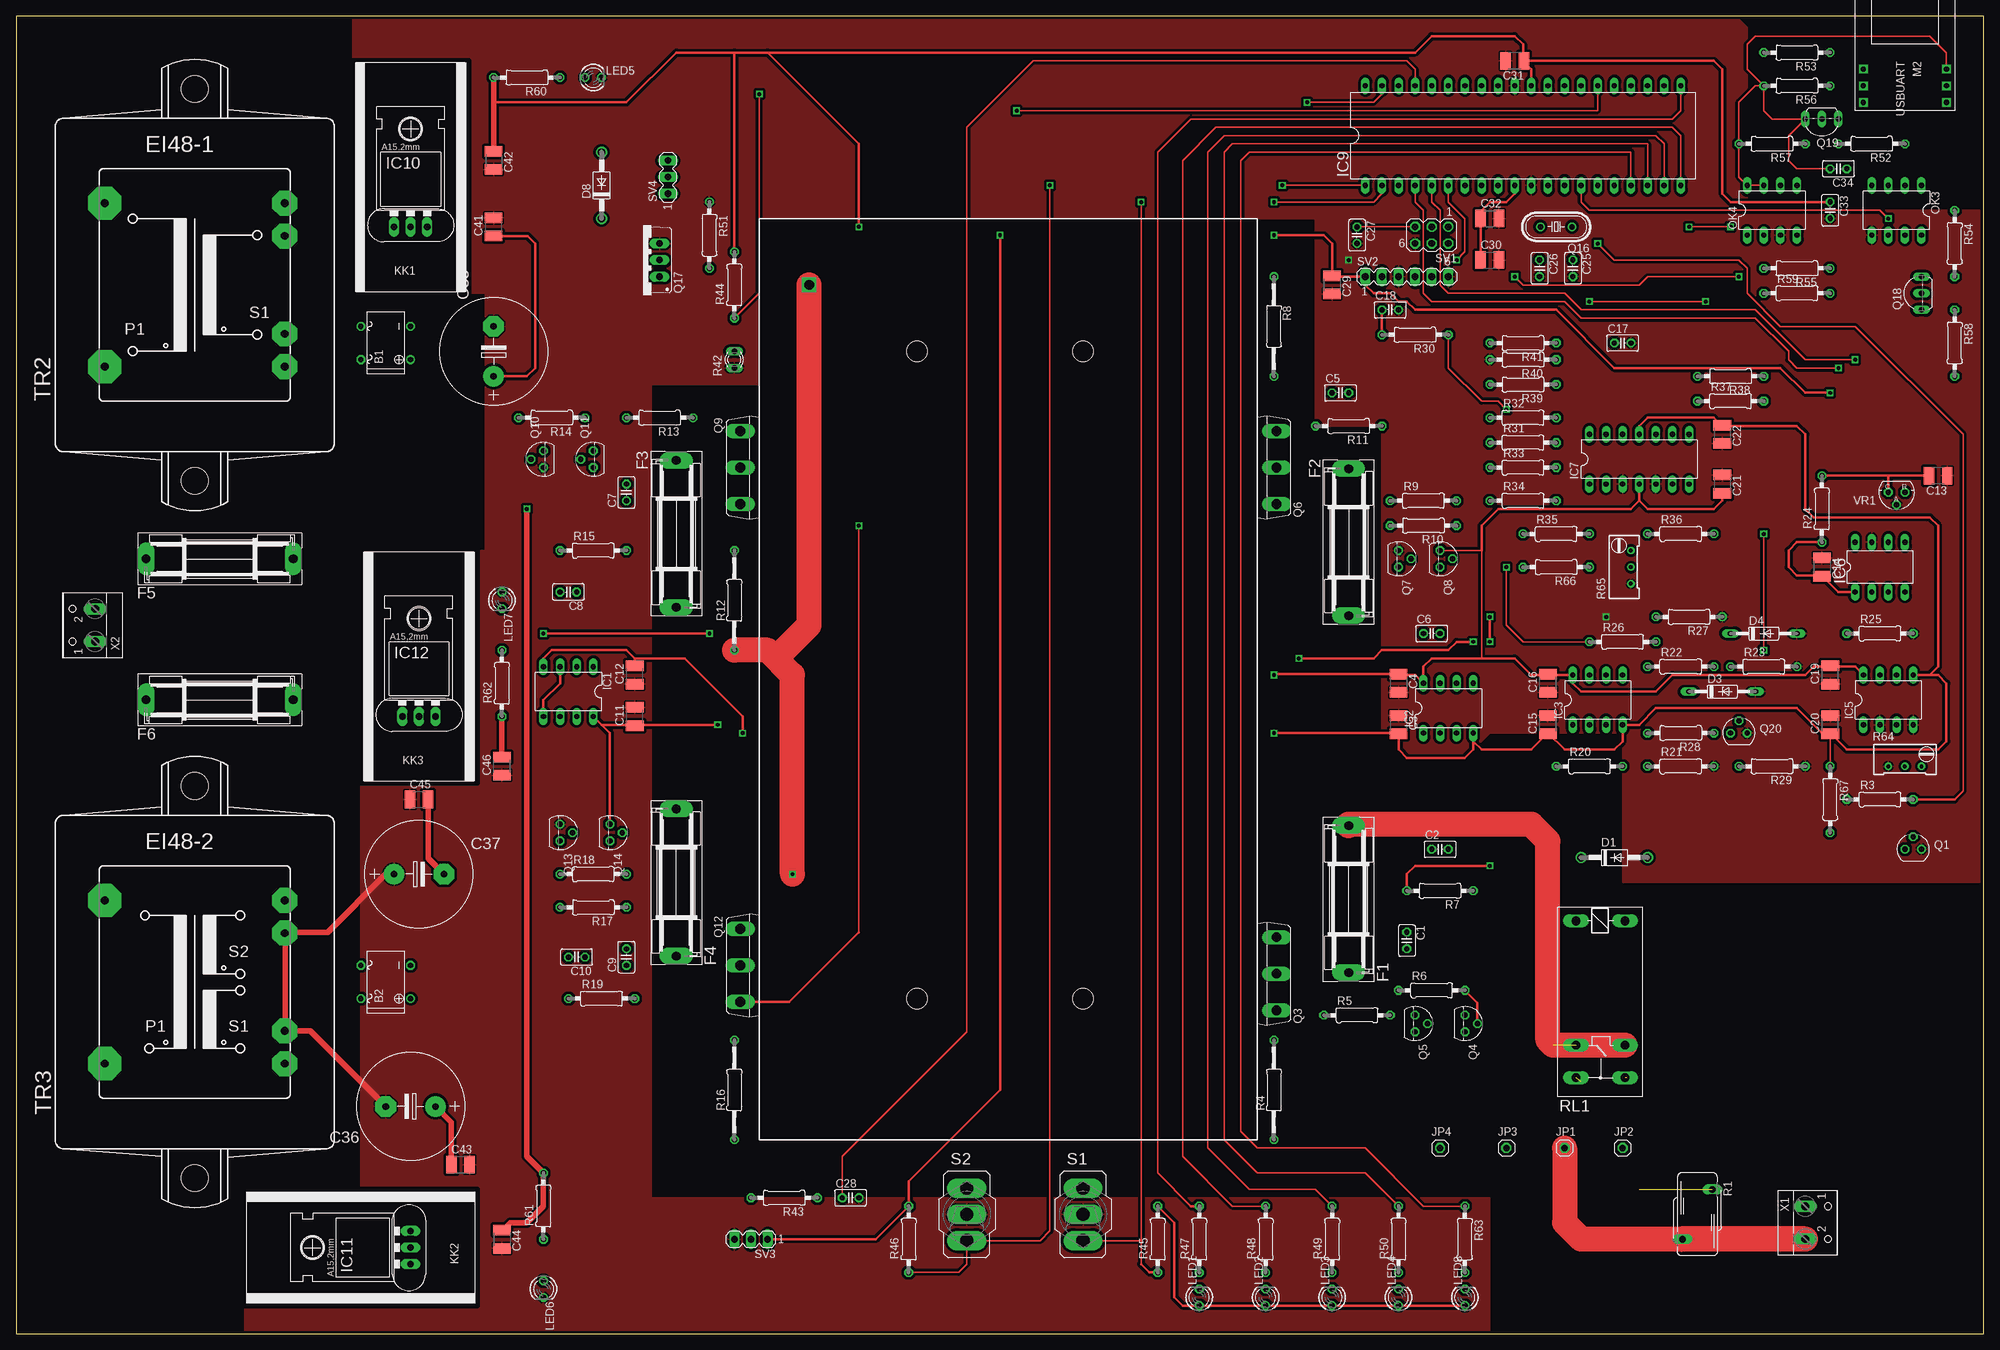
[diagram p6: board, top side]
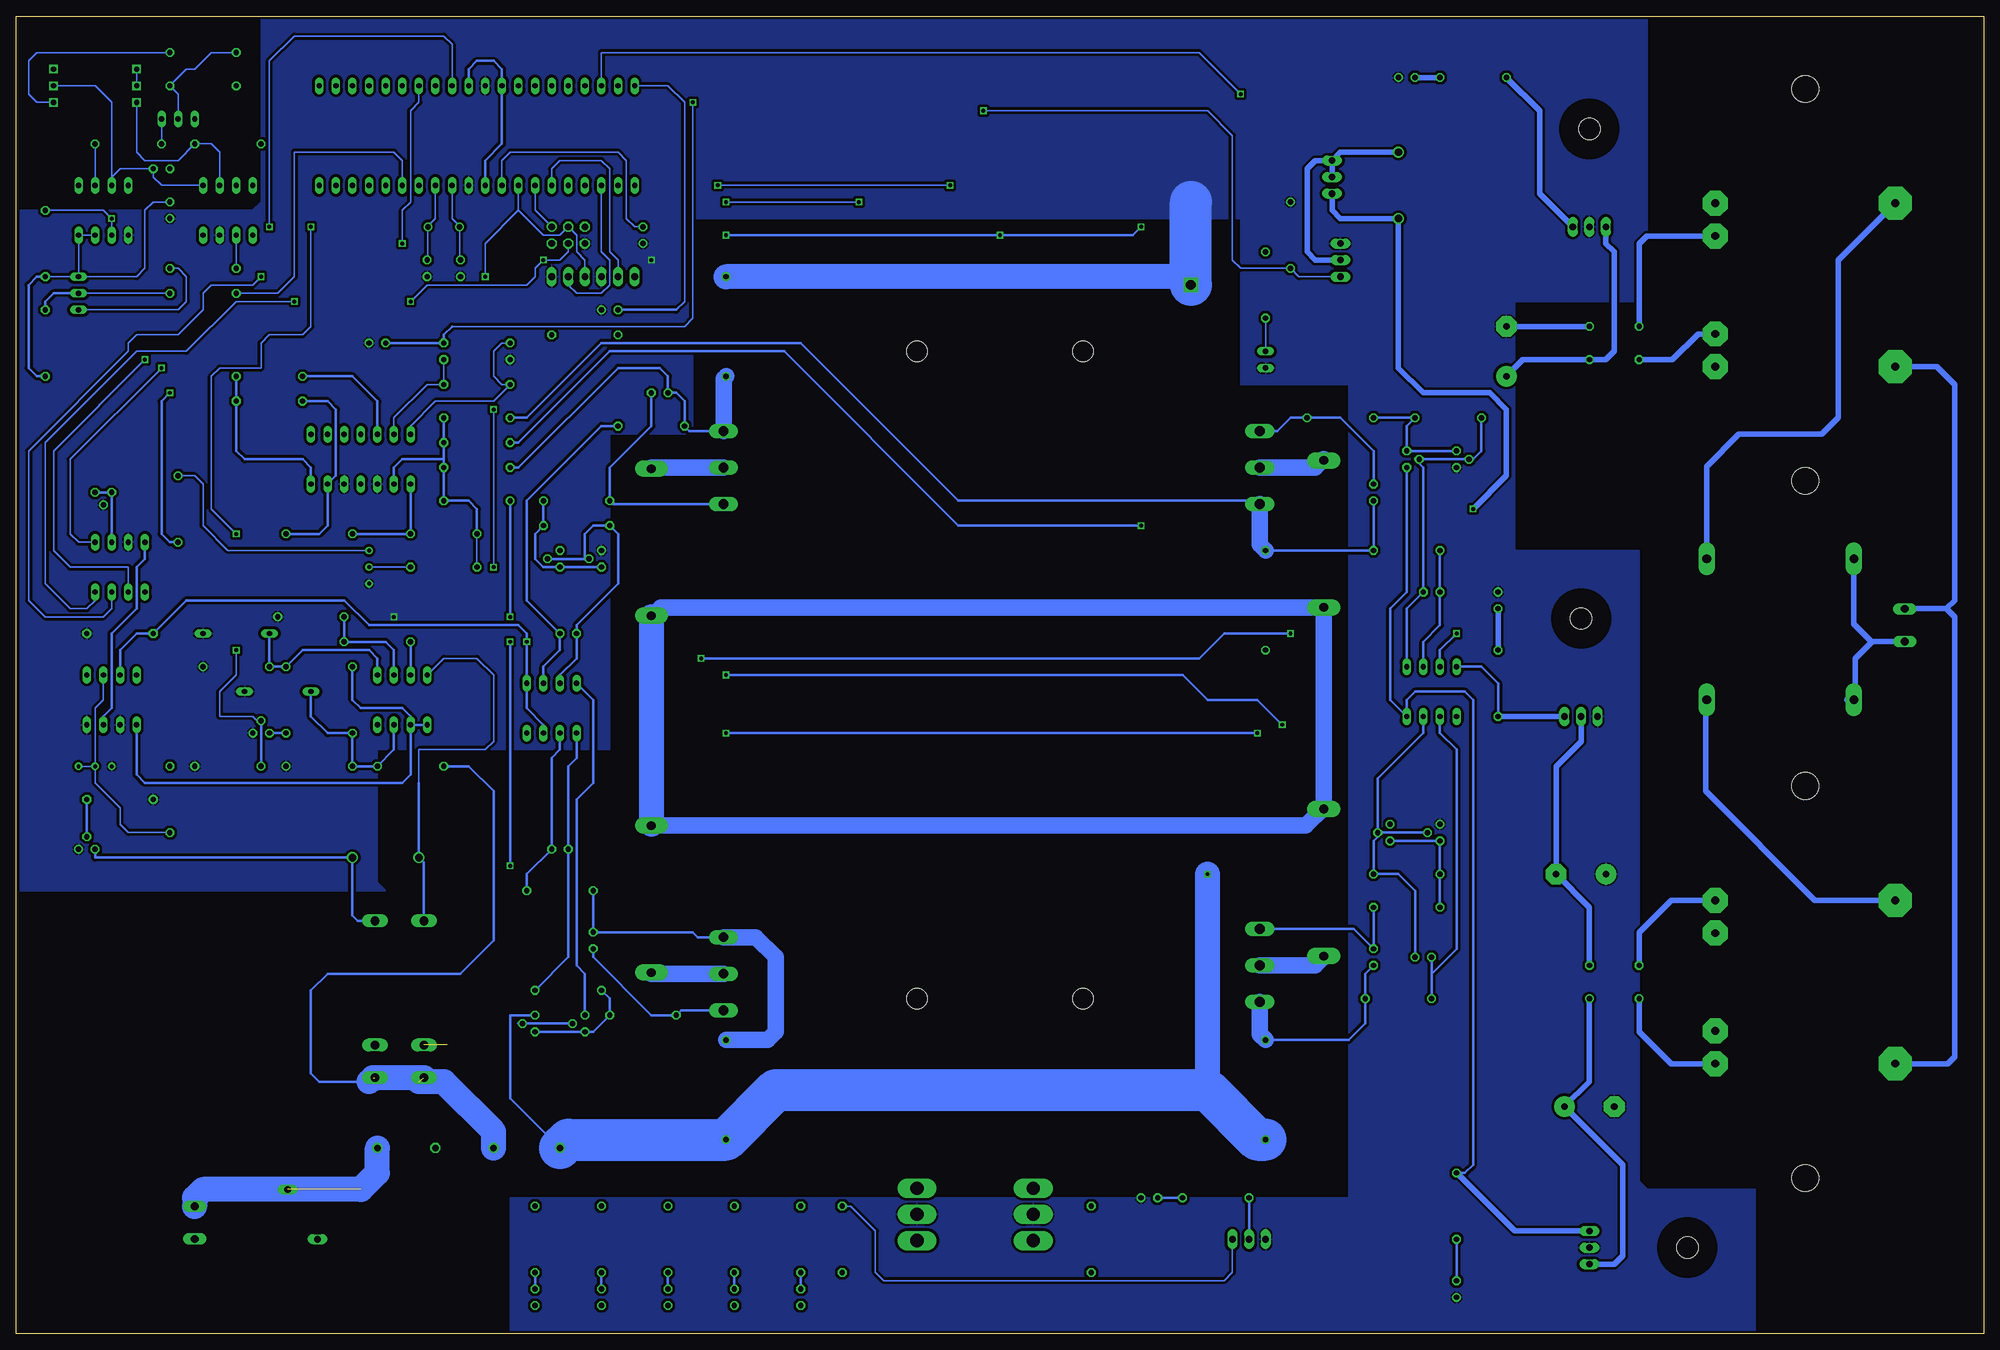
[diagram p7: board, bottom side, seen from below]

Size 300.97 x 201.6 mm. Coordinates in mm from the lower left corner, seen from the top.
Outline: 0,0 300.97,0 300.97,201.6 0,201.6 0,0
Copper layers (1*16): Top 0.035mm / dielectric 1.5mm / Bottom 0.035mm
Design rules "default": minimum track width 10mil, minimum drill 6mil, track to track 6mil, track to pad 6mil, pad to pad 6mil, via to via 6mil, smd to smd 6mil, copper to edge 6mil, drill to drill 6mil, minimum pad ring 10mil, minimum via ring 8mil, stop-mask expansion 4mil, vias tented up to drill 0mil, thermal gap 10mil
Holes 3.2 mm at 137.79,150.33 137.79,51.27 163.19,150.33 163.19,51.27

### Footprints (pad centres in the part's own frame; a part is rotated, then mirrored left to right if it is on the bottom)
B-DIL = drill 0.813 round: + -2.54,-3.81 | drill 0.813 octagon: - 2.54,-3.81; AC1 2.54,3.81; AC2 -2.54,3.81
C025-025X050 = drill 0.813 octagon: 1 -1.27,0; 2 1.27,0
C1210 = smd 1.6 x 2.7: 1 -1.4,0; 2 1.4,0
E7,5-16 = drill 1.016 pad 3.15 round: + -3.81,0 | drill 1.016 pad 3.15 octagon: - 3.81,0
DO41-10 = drill 1.118 round: A 5.08,0; C -5.08,0
DO35Z10 = drill 0.813 long: A 5.08,0; C -5.08,0
SH22,5 = drill 1.321 pad 2.54 long: 1 -11.252,0; 2 11.252,0
DIL08 = drill 0.813 long: 1 -3.81,-3.81; 2 -1.27,-3.81; 3 1.27,-3.81; 4 3.81,-3.81; 5 3.81,3.81; 6 1.27,3.81; 7 -1.27,3.81; 8 -3.81,3.81
DIL8 = drill 0.813 long: 1 -3.81,-3.81; 2 -1.27,-3.81; 3 1.27,-3.81; 4 3.81,-3.81; 5 3.81,3.81; 6 1.27,3.81; 7 -1.27,3.81; 8 -3.81,3.81
DIL14 = drill 0.813 long: 1 -7.62,-3.81; 2 -5.08,-3.81; 3 -2.54,-3.81; 4 0,-3.81; 5 2.54,-3.81; 6 5.08,-3.81; 7 7.62,-3.81; 8 7.62,3.81; 9 5.08,3.81; 10 2.54,3.81; 11 0,3.81; 12 -2.54,3.81; 13 -5.08,3.81; 14 -7.62,3.81
DIL40 = drill 0.813 long: 1 -24.13,-7.62; 2 -21.59,-7.62; 3 -19.05,-7.62; 4 -16.51,-7.62; 5 -13.97,-7.62; 6 -11.43,-7.62; 7 -8.89,-7.62; 8 -6.35,-7.62; 9 -3.81,-7.62; 10 -1.27,-7.62; 11 1.27,-7.62; 12 3.81,-7.62; 13 6.35,-7.62; 14 8.89,-7.62; 15 11.43,-7.62; 16 13.97,-7.62; 17 16.51,-7.62; 18 19.05,-7.62; 19 21.59,-7.62; 20 24.13,-7.62; 21 24.13,7.62; 22 21.59,7.62; 23 19.05,7.62; 24 16.51,7.62; 25 13.97,7.62; 26 11.43,7.62; 27 8.89,7.62; 28 6.35,7.62; 29 3.81,7.62; 30 1.27,7.62; 31 -1.27,7.62; 32 -3.81,7.62; 33 -6.35,7.62; 34 -8.89,7.62; 35 -11.43,7.62; 36 -13.97,7.62; 37 -16.51,7.62; 38 -19.05,7.62; 39 -21.59,7.62; 40 -24.13,7.62
78XXL = drill 1.016 long: GND 0,-3.81; IN -2.54,-3.81; OUT 2.54,-3.81 | hole 3.302: 0,11.176
79XXL = drill 1.016 long: GND -2.54,-3.81; IN 0,-3.81; OUT 2.54,-3.81 | hole 3.302: 0,11.176
1X01 = drill 1.016 octagon: 1 0,0
LED3MM = drill 0.813 octagon: A -1.27,0; K 1.27,0
USBUART = drill 0.8 square: 1 2.54,-6.35; 2 5.08,-6.35; 3 7.62,-6.35; 4 7.62,6.35; 5 5.08,6.35; 6 2.54,6.35
SOT54E = drill 0.813 octagon: D -1.27,0; G 0,1.905; S 1.27,0
TO247BV = drill 1.499 long: D 0,-2.921; G -5.588,-2.921; S 5.588,-2.921
TO92 = drill 0.813 octagon: 1 1.27,0; 2 0,1.905; 3 -1.27,0
HC49/S = drill 0.813 round: 1 -2.413,0; 2 2.413,0
TO220BV = drill 1.016 long: D 0,-2.54; G -2.54,-2.54; S 2.54,-2.54
TO92-EBC = drill 0.813 long: B 0,-1.27; C -2.54,-1.27; E 2.54,-1.27
S10K420 = drill 1.016 long: 1 -2.286,-3.81; 2 2.286,3.81
0207/10 = drill 0.813 octagon: 1 -5.08,0; 2 5.08,0
0207/15 = drill 0.813 octagon: 1 -7.62,0; 2 7.62,0
P640 = drill 0.813 long: 1 -1.27,0; 2 1.27,0
RTRIM64W = drill 0.61 round: 1 1.27,-2.54; 2 1.27,0; 3 1.27,2.54
FIN43619 = drill 1.321 long: 1 2.07,3.047; 2 2.07,10.54; P 21.06,3.047; P@ 21.06,10.54; S 26.064,3.047; S@ 26.064,10.54
320-916 = drill 2.007 long: 1 0,4.013; 2 0,0; 3 0,-4.013
MA03-2 = drill 1.016 round: 1 -2.54,-1.27 | drill 1.016 octagon: 2 -2.54,1.27; 3 0,-1.27; 4 0,1.27; 5 2.54,-1.27; 6 2.54,1.27
MA06-1 = drill 1.016 long: 1 -6.35,0; 2 -3.81,0; 3 -1.27,0; 4 1.27,0; 5 3.81,0; 6 6.35,0
MA03-1 = drill 1.016 long: 1 -2.54,0; 2 0,0; 3 2.54,0
EI48-1B = drill 1.194 pad 5.08 octagon: 1 -13.767,12.497; 6 -13.767,-12.497 | drill 1.194 pad 3.81 octagon: 7 13.767,-12.497; 8 13.767,-7.493; 11 13.767,7.493; 12 13.767,12.497 | hole 4.115: 0,-29.997; 0,29.997
EI48-2B = drill 1.194 pad 5.08 octagon: 1 -13.767,12.497; 6 -13.767,-12.497 | drill 1.194 pad 3.81 octagon: 7 13.767,-12.497; 8 13.767,-7.493; 11 13.767,7.493; 12 13.767,12.497 | hole 4.115: 0,-29.997; 0,29.997
TO92-CLP = drill 0.813 octagon: A 0,1.905; C 1.27,0; R -1.27,0
W237-102 = drill 1.194 long: 1 -2.5,-1.27; 2 2.5,-1.27

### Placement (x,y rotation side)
B1  56.51,151.6 90 top
B2  56.51,53.81 90 top
C1  212.72,60.16 270 top
C2  217.8,74.13 0 top
C3  211.45,93.18 270 top
C4  211.45,99.53 270 top
C5  202.56,143.98 0 top
C6  216.53,107.15 0 top
C7  93.34,128.74 90 top
C8  84.45,113.5 180 top
C9  93.34,57.62 90 top
C10  85.72,57.62 180 top
C11  94.61,94.45 90 top
C12  94.61,100.8 90 top
C13  294,131.28 180 top
C14  276.22,117.31 270 top
C15  234.31,93.18 90 top
C16  234.31,99.53 90 top
C17  245.74,151.6 0 top
C18  210.18,156.68 0 top
C19  277.49,100.8 90 top
C20  277.49,93.18 90 top
C21  260.98,130.01 270 top
C22  260.98,137.63 270 top
C25  238.12,163.03 270 top
C26  233.04,163.03 270 top
C27  205.1,168.11 270 top
C28  127.63,20.79 0 top
C29  201.29,160.49 270 top
C30  225.42,164.3 0 top
C31  229.23,194.78 180 top
C32  225.42,170.65 0 top
C33  277.49,171.92 270 top
C34  278.76,178.27 180 top
C35  73.02,150.33 90 top
C36  60.32,34.76 180 top
C37  61.59,70.32 0 top
C41  73.02,169.38 90 top
C42  73.02,179.54 270 top
C43  67.94,25.87 0 top
C44  74.29,14.44 270 top
C45  61.59,81.75 0 top
C46  74.29,86.83 90 top
D1  244.47,72.86 0 top
D3  260.98,98.26 0 top
D4  267.33,107.15 0 top
D8  89.53,175.73 90 top
F1  203.83,66.51 90 top
F2  203.83,121.12 270 top
F3  100.96,122.39 270 top
F4  100.96,69.05 90 top
F5  31.11,118.58 0 top
F6  31.11,96.99 0 top
IC1  84.45,98.26 180 top
IC2  219.07,95.72 0 top
IC3  241.93,96.99 0 top
IC5  286.38,96.99 0 top
IC6  285.11,117.31 0 top
IC7  248.28,133.82 0 top
IC9  230.5,183.35 0 top
IC10  60.32,173.19 0 top
IC11  56.51,13.17 90 top
IC12  61.59,98.26 0 top
JP1  236.85,28.41 0 top
JP2  245.74,28.41 0 top
JP3  227.96,28.41 0 top
JP4  217.8,28.41 0 top
KK1  60.32,173.19 270 top
KK2  56.51,13.17 0 top
KK3  61.59,98.26 270 top
LED1  180.97,5.55 90 top
LED2  191.13,5.55 90 top
LED3  201.29,5.55 90 top
LED4  211.45,5.55 90 top
LED5  88.26,192.24 0 top
LED6  80.64,6.82 270 top
LED7  74.29,112.23 270 top
LED8  221.61,5.55 90 top
M2  288.92,196.05 270 top
OK3  287.65,171.92 180 top
OK4  268.6,171.92 0 top
Q1  290.19,74.13 0 top
Q3  189.86,55.08 90 top
Q4  221.61,47.46 270 top
Q5  213.99,47.46 270 top
Q6  189.86,132.55 90 top
Q7  211.45,118.58 270 top
Q8  217.8,118.58 270 top
Q9  113.66,132.55 270 top
Q10  80.64,133.82 90 top
Q11  88.26,133.82 90 top
Q12  113.66,56.35 270 top
Q13  83.18,76.67 270 top
Q14  90.8,76.67 270 top
Q16  235.58,169.38 180 top
Q17  95.88,164.3 90 top
Q18  290.19,159.22 90 top
Q19  276.22,184.62 180 top
Q20  263.52,91.91 0 top
R1  257.17,18.25 180 top
R3  285.11,81.75 0 top
R4  192.4,37.3 90 top
R5  205.1,48.73 0 top
R6  216.53,52.54 0 top
R7  217.8,67.78 180 top
R8  192.4,154.14 270 top
R9  215.26,127.47 0 top
R10  215.26,123.66 180 top
R11  203.83,138.9 180 top
R12  109.85,112.23 90 top
R13  98.42,140.17 180 top
R14  81.91,140.17 180 top
R15  88.26,119.85 0 top
R16  109.85,37.3 90 top
R17  88.26,65.24 180 top
R18  88.26,70.32 0 top
R19  89.53,51.27 0 top
R20  240.66,86.83 0 top
R21  254.63,86.83 0 top
R22  254.63,102.07 0 top
R23  267.33,102.07 0 top
R24  276.22,126.2 90 top
R25  285.11,107.15 0 top
R26  245.74,105.88 0 top
R27  255.9,109.69 180 top
R28  254.63,91.91 180 top
R29  268.6,86.83 180 top
R30  213.99,152.87 180 top
R31  230.5,136.36 0 top
R32  230.5,140.17 0 top
R33  230.5,132.55 0 top
R34  230.5,127.47 0 top
R35  235.58,122.39 0 top
R36  254.63,122.39 0 top
R37  262.25,142.71 0 top
R38  262.25,146.52 180 top
R39  230.5,145.25 180 top
R40  230.5,149.06 180 top
R41  230.5,151.6 180 top
R42  109.85,149.06 90 top
R43  117.47,20.79 180 top
R44  109.85,160.49 90 top
R45  174.62,14.44 90 top
R46  136.52,14.44 90 top
R47  180.97,14.44 90 top
R48  191.13,14.44 90 top
R49  201.29,14.44 90 top
R50  211.45,14.44 90 top
R51  106.04,168.11 270 top
R52  283.84,182.08 180 top
R53  272.41,196.05 180 top
R54  296.54,166.84 270 top
R55  272.41,163.03 180 top
R56  272.41,190.97 180 top
R57  268.6,182.08 180 top
R58  296.54,151.6 270 top
R59  272.41,159.22 0 top
R60  78.1,192.24 180 top
R61  80.64,19.52 90 top
R62  74.29,99.53 90 top
R63  221.61,14.44 270 top
R64  288.92,88.1 270 top
R65  245.74,117.31 0 top
R66  235.58,117.31 180 top
R67  277.49,81.75 270 top
RL1  235.58,65.24 270 top
S1  163.19,18.25 0 top
S2  145.41,18.25 0 top
SV1  216.53,168.11 180 top
SV2  212.72,161.76 0 top
SV3  112.39,14.44 180 top
SV4  99.69,177 90 top
TR2  27.3,160.49 0 top
TR3  27.3,53.81 0 top
VR1  287.65,128.74 180 top
X1  274.95,16.98 270 top
X2  10.79,108.42 90 top

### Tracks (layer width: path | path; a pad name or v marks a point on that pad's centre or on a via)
+5V  (via drill 0.6)
  Top 0.406: C33.1 262.25,173.19 260.98,174.46 260.98,193.51 259.71,194.78 C31.1 230.5,194.78 | IC9.30 231.77,193.51 230.5,194.78 | C30.1 224.02,170.52 224.15,170.65 C32.1 224.02,171.79 225.42,173.19 227.96,173.19 229.23,174.46 IC9.10 | 201.29,161.76 C29.1 | 201.29,161.76 SV2.1 206.37,160.49 207.64,159.22 210.18,159.22 211.45,157.95 212.72,157.95 213.99,156.68 235.58,156.68 244.47,147.79 269.87,147.79 273.68,143.98 v277.49,143.98 | 201.29,161.76 201.29,166.84 200.02,168.11 v192.4,168.11 | v128.9,169.38 128.9,182.08 114.93,196.05 | 109.85,196.05 100.96,196.05 93.34,188.43 73.02,188.43 | 109.85,196.05 R44.2 | 114.93,196.05 213.99,196.05 216.53,198.59 229.23,198.59 230.5,197.32 230.5,194.78 | 109.85,196.05 114.93,196.05 | LED8.A LED4.A LED3.A LED2.A LED1.A 178.43,4.28 177.16,5.55 177.16,16.98 R45.2 | v150.49,168.11 150.49,37.3 136.52,23.33 R46.2 131.44,14.44 SV3.1 | IC6.1 278.76,113.5 276.22,116.04 | R24.1 272.41,121.12 271.14,119.85 271.14,117.31 272.41,116.04 276.22,116.04 | 276.22,116.04 C14.2
  Top 0.813: R60.2 73.02,188.43 C42.1
  Bottom 0.254: Q18.E R54.2 | Q18.E OK3.8 OK3.7 | Q18.E 282.57,161.76 281.3,163.03 281.3,171.92 280.03,173.19 C33.1 | R45.2 173.35,19.52 169.54,15.71 169.54,9.36 168.27,8.09 116.2,8.09 114.93,9.36 SV3.1
  Bottom 0.406: IC9.30 231.77,193.51 230.5,194.78 227.96,194.78 226.69,193.51 IC9.32 226.69,182.08 229.23,179.54 IC9.10 | v192.4,168.11 v150.49,168.11 130.17,168.11 v128.9,169.38 | R54.2 297.81,161.76 299.08,160.49 299.08,147.79 297.81,146.52 R58.2 | R24.1 277.49,121.12 278.76,122.39 278.76,142.71 v277.49,143.98
  Bottom 0.813: IC10.OUT 67.94,174.46 67.94,187.16 R60.2
+12V  (via drill 0.6)
  Top 0.254: Q8.3 224.15,119.85 224.15,103.34
  Top 0.406: IC1.8 89.53,93.18 | 89.53,93.18 94.61,93.18 | Q14.3 90.8,91.91 89.53,93.18 | 94.61,93.18 C11.1 | 94.61,93.18 v107.31,93.18 | 234.31,100.8 C16.2 | 234.31,100.8 IC3.8 238.12,99.53 239.39,98.26 250.82,98.26 253.36,100.8 273.68,100.8 274.95,102.07 277.49,102.07 | 234.31,100.8 231.77,100.8 229.23,103.34 224.15,103.34 216.53,103.34 215.26,102.07 IC2.8 213.99,100.8 211.45,100.8 C4.1 192.53,100.93 v192.4,100.8 | IC5.8 281.3,102.07 277.49,102.07 | 277.49,102.07 C19.2 | C21.2 260.98,127.47 259.71,126.2 249.55,126.2 248.28,127.47 | 248.28,127.47 IC7.4 | 248.28,127.47 247.01,126.2 226.69,126.2 224.15,123.66 224.15,119.85
  Top 0.813: C44.1 74.29,15.71 75.56,16.98 78.1,16.98 80.64,19.52 R61.2 78.1,27.14 v78.1,126.2
  Bottom 0.254: 239.39,84.29 239.39,89.37 229.23,89.37 227.96,90.64 227.96,100.8 230.5,103.34 235.58,103.34 IC3.8
  Bottom 0.406: R61.2 79.37,24.6 78.1,25.87 78.1,96.99 79.37,98.26 86.99,98.26 88.26,96.99 IC1.8 90.8,96.99 90.8,110.96 88.26,113.5 Q11.3 | v107.31,93.18 111.12,96.99 118.74,96.99 122.55,100.8 v192.4,100.8 | Q5.3 213.99,55.08 215.26,56.35 215.26,81.75 212.72,84.29 212.72,96.99 IC2.8 | RL1.1 238.63,72.1 D1.C 239.39,84.29
  Bottom 0.813: IC11.OUT 71.75,15.71 R61.2 | SV4.1 99.69,171.92 98.42,170.65 D8.C 89.53,147.79 85.72,143.98 75.56,143.98 73.02,141.44 73.02,131.28 v78.1,126.2
-12V  (via drill 0.6)
  Top 0.254: 260.98,138.9 259.71,140.17 | 277.49,91.91 R67.1
  Top 0.406: 94.61,103.34 C12.2 | 94.61,103.34 93.34,104.61 81.91,104.61 80.64,103.34 IC1.4 | 94.61,103.34 102.23,103.34 111.12,94.45 v111.12,91.91 | 234.31,91.91 231.77,89.37 224.15,89.37 222.88,90.64 IC2.4 222.88,89.37 221.61,88.1 212.72,88.1 211.45,89.37 C3.2 211.45,91.91 v192.4,91.91 | 234.31,91.91 C15.1 | 234.31,91.91 236.85,89.37 244.47,89.37 245.74,90.64 IC3.4 248.28,93.18 250.82,95.72 272.41,95.72 276.22,91.91 277.49,91.91 | 292.73,100.8 294,100.8 295.27,99.53 295.27,90.64 294,89.37 280.03,89.37 277.49,91.91 | 292.73,100.8 IC5.5 | 277.49,91.91 C20.1 | IC7.11 248.28,138.9 249.55,140.17 259.71,140.17 | C22.1 260.98,138.9 272.41,138.9 273.68,137.63 273.68,126.2 274.95,124.93 292.73,124.93 294,123.66 294,102.07 292.73,100.8
  Top 0.813: 74.29,88.1 C46.2 R62.1
  Bottom 0.406: IC1.4 76.83,102.07 74.29,99.53 R62.1 | v192.4,91.91 v111.12,91.91
  Bottom 0.813: R62.1 IC12.OUT
CS_DAC  (via drill 0.6)
  Top 0.254: IC9.5 216.53,173.19 217.8,171.92 217.8,160.49 219.07,159.22 236.85,159.22 239.39,156.68 266.06,156.68 273.68,149.06 v281.3,149.06
  Bottom 0.254: IC6.2 283.84,117.31 292.73,117.31 295.27,119.85 295.27,135.09 v281.3,149.06
GAIN  (via drill 0.6)
  Top 0.254: v255.9,169.38 v262.25,169.38 | v267.33,104.61 v267.33,122.39
  Bottom 0.254: IC9.29 234.31,197.32 235.58,198.59 258.44,198.59 262.25,194.78 v262.25,169.38 | v255.9,169.38 255.9,154.14 257.17,152.87 262.25,152.87 263.52,151.6 263.52,147.79 269.87,147.79 271.14,146.52 271.14,126.2 v267.33,122.39 | v267.33,104.61 267.33,100.8 269.87,98.26 269.87,94.45 264.79,94.45 263.52,93.18
  Bottom 0.406: R29.2 263.52,93.18 Q20.G
GND  (via drill 0.6, 1.5)
  Top 0.406: C32.2 226.69,170.65 226.82,170.52
  Top 0.813: C37.+ 56.51,70.32 47.62,61.43 41.27,61.43 41.14,61.3 | 41.14,61.3 TR3.11 | 41.14,46.32 TR3.8 44.95,46.32 C36.- | 41.14,46.32 41.14,61.3 | 41.14,46.32 41.27,46.19
  Top 2.54: R12.1 117.47,104.61
  Top 3.81: v121.28,160.49 121.28,108.42 117.47,104.61 | R12.1 114.93,104.61 118.74,100.8 v118.74,70.32
  Bottom 0.406: Q4.3 225.42,48.73 225.42,37.3 225.42,36.03 JP4.1
  Bottom 0.813: B1.- C35.-
  Bottom 2.54: v121.28,160.49 122.55,161.76
  Bottom 3.81: 122.55,161.76 R8.1 | v118.74,70.32 118.74,38.57 R16.1
  Bottom 6.452: JP4.1 216.53,29.68 R4.1 184.78,37.3 118.74,37.3 111.12,29.68 R16.1 | v121.28,160.49 121.28,173.19
  other vias: 203.83,164.3 243.2,109.69
  pour Bottom (isolate 0.406): 51.43,201.13 51.43,157.95 71.75,157.95 71.75,119.85 52.7,119.85 52.7,23.33 51.43,22.06 34.92,22.06 34.92,0.47 225.42,0.47 225.42,20.79 97.15,20.79 97.15,145.25 113.66,145.25 113.66,170.65 197.48,170.65 197.48,137.63 210.18,137.63 210.18,89.37 245.74,89.37 245.74,69.05 244.47,67.78 300.35,67.78 300.35,171.92 264.79,171.92 263.52,173.19 263.52,201.13
  pour Top (isolate 0.406): 51.43,201.13 51.43,160.49 52.7,159.22 71.75,159.22 71.75,119.85 52.7,119.85 52.7,22.06 34.92,22.06 34.92,0.47 225.42,0.47 225.42,20.79 97.15,20.79 97.15,145.25 113.66,145.25 113.66,170.65 198.75,170.65 198.75,138.9 208.91,138.9 208.91,88.1 221.61,88.1 225.42,91.91 245.74,91.91 245.74,69.05 300.35,69.05 300.35,171.92 264.79,171.92 264.79,199.86 263.52,201.13
I1IST  (via drill 0.6)
  Top 0.254: v128.9,123.66 128.9,61.43
  Top 0.406: Q12.S 118.23,50.76 128.9,61.43
  Bottom 0.406: R16.2 97.15,44.92 94.61,47.46 R19.2 94.61,55.08 C9.1 | R31.1 224.15,136.36 210.18,150.33 183.51,150.33 156.84,123.66 v128.9,123.66
  Bottom 2.54: Q12.S 110.74,45.81 R16.2
I2IST
  Bottom 0.406: R12.2 R15.2 C7.1 | R32.1 222.88,140.17 211.45,151.6 180.97,151.6 156.84,127.47 112.39,127.47 111.12,126.2 110.74,126.2
  Bottom 2.54: Q9.S 110.74,126.2 110.74,120.74 R12.2
I3IST
  Bottom 0.406: Q6.S 197.99,138.14 R11.2 198.75,142.71 200.02,143.98 C5.1 201.29,146.52 202.56,147.79 208.91,147.79 224.15,132.55 R33.1
  Bottom 2.54: Q6.S 192.78,146.14 R8.2
I4IST  (via drill 0.6)
  Top 0.406: v225.42,105.88 v225.42,109.69 | v225.42,71.59 213.99,71.59 212.72,70.32 R7.2
  Bottom 0.406: R7.2 C1.1 197.48,61.43 196.72,60.67 Q3.S | v225.42,109.69 R34.1 | v225.42,71.59 v225.42,105.88
  Bottom 2.54: R4.2 186.05,44.92 184.78,46.19 184.78,57.62 187.83,60.67 Q3.S
IIST_ADC  (via drill 0.6)
  Top 0.254: v197.48,188.43 207.64,188.43 208.91,189.7 IC9.39
  Bottom 0.254: 234.31,154.14 198.75,154.14 197.48,155.41 v197.48,188.43
  Bottom 0.406: 234.31,154.14 235.58,152.87 R41.1 C17.1
ISOLL  (via drill 0.6)
  Top 0.406: IC1.5 80.64,96.99 83.18,99.53 IC1.3 | v222.88,105.88 220.34,105.88 219.07,104.61 208.91,104.61 207.64,103.34 v196.21,103.34 | v106.04,107.15 v80.64,107.15
  Bottom 0.406: IC1.3 83.18,104.61 v80.64,107.15 | IC2.3 220.34,93.18 222.88,95.72 IC2.5 v222.88,105.88 222.88,107.15 224.15,108.42 247.01,108.42 250.82,112.23 274.95,112.23 R25.1 282.57,107.15 285.11,104.61 IC5.7 | v196.21,103.34 120.01,103.34 116.2,107.15 v106.04,107.15
LDAC  (via drill 0.6)
  Top 0.254: IC9.4 213.99,173.19 215.26,171.92 215.26,159.22 216.53,157.95 236.85,157.95 239.39,155.41 266.06,155.41 271.14,150.33 271.14,149.06 272.41,147.79 v278.76,147.79
  Bottom 0.254: IC6.5 291.46,121.12 292.73,122.39 292.73,133.82 v278.76,147.79
MISO
  Bottom 0.254: IC9.7 221.61,171.92 SV1.1
MOSI  (via drill 0.6)
  Top 0.254: IC9.6 219.07,173.19 221.61,170.65 221.61,165.57 v220.34,164.3 | v240.66,157.95 v258.44,157.95
  Bottom 0.254: SV2.2 208.91,164.3 210.18,165.57 210.18,178.27 211.45,179.54 217.8,179.54 219.07,178.27 IC9.6 | IC6.4 288.92,112.23 290.19,110.96 292.73,110.96 296.54,114.77 296.54,136.36 282.57,150.33 274.95,150.33 267.33,157.95 v258.44,157.95 | SV1.4 216.53,165.57 217.8,164.3 v220.34,164.3 221.61,163.03 221.61,161.76 222.88,160.49 238.12,160.49 v240.66,157.95
N$1  (1 unrouted)
  Bottom 3.81: X1.1 273.68,20.79 272.41,22.06 248.28,22.06 245.74,24.6 JP2.1
N$2
  Top 3.81: R1.2 254.63,14.44 254.67,14.48 X1.2 239.35,14.48 236.85,16.98 JP1.1
N$4
  Bottom 0.406: Q1.D 288.92,72.86 D1.A 249.55,63.97 248.75,63.17 RL1.2
N$6
  Bottom 0.254: R64.2 R64.3 | IC5.6 287.65,96.99 288.92,95.72 R64.2 | R67.2 283.84,76.67 285.11,77.94 285.11,80.48 288.92,84.29 R64.2
N$7  (via drill 0.6)
  Top 0.254: v113.66,189.7 113.66,159.22 R44.1
  Bottom 0.254: R42.2 R44.1 | IC9.38 211.45,196.05 120.01,196.05 v113.66,189.7
N$8
  Bottom 2.54: F1.1 203.83,55.08 Q3.D
N$10
  Bottom 0.406: D3.C 255.9,94.45 253.36,91.91 R28.2 R21.1 R20.2 243.2,89.37 IC3.3
N$11
  Bottom 0.406: Q3.G 199.26,49.49 R5.1 203.83,48.73 212.72,57.62 C1.2
N$12
  Bottom 0.406: R6.1 210.18,51.27 R5.2 212.72,46.19 Q5.1 Q4.1
N$13
  Top 0.406: Q4.2 223.51,50.63 R6.2
  Bottom 0.406: Q5.2 Q4.2 224.15,47.46 | R6.2 216.53,57.62 C2.1 216.53,86.83 215.26,88.1 IC2.1
N$14
  Bottom 0.406: R28.1 Q20.D
N$15
  Bottom 0.406: R7.1 222.88,70.32 C2.2 219.07,88.1 217.8,89.37 IC2.2
N$16
  Bottom 2.54: F2.1 203.83,132.55 Q6.D
N$17
  Bottom 0.406: IC3.2 IC3.1 | R22.1 249.55,96.99 248.28,95.72 241.93,95.72 240.66,94.45 IC3.2 | IC5.1 282.57,85.56 281.3,84.29 241.93,84.29 240.66,85.56 IC3.2
N$18
  Bottom 0.406: Q6.G 209.67,126.96 R9.1 210.18,132.55 203.83,138.9 C5.2
N$19
  Bottom 0.406: R9.2 R10.1 221.61,122.39 221.61,118.58 220.34,117.31 Q8.1 Q7.1
N$20
  Bottom 0.406: 213.99,118.58 213.99,122.39 212.72,123.66 R10.2 208.91,122.39 208.91,114.77 215.26,108.42 C6.1 215.26,103.34 217.8,100.8 IC2.7 | 213.99,118.58 Q8.2 | 213.99,118.58 Q7.2
N$21
  Bottom 0.406: IC2.6 220.34,102.07 217.8,104.61 C6.2 222.88,112.23 222.88,127.47 211.45,138.9 R11.1
N$22
  Bottom 2.54: F3.1 100.96,133.82 102.23,132.55 Q9.D
N$23
  Bottom 0.406: D4.C R23.1 R22.2 257.17,104.61 247.01,104.61 245.74,103.34 IC3.5
N$24
  Bottom 0.406: Q9.G 108.07,138.14 106.04,140.17 R13.1 98.42,140.17 93.34,135.09 C7.2
N$25
  Bottom 0.406: R13.2 R14.1 88.26,138.9 Q11.1 Q10.1
N$26
  Bottom 0.406: R14.2 76.83,135.09 78.1,133.82 Q10.2 79.37,133.82 Q11.2 86.99,133.82 85.72,132.55 C8.1 88.26,110.96 IC1.1
N$27
  Bottom 0.406: R15.1 C8.2 83.18,108.42 85.72,105.88 IC1.2
N$28
  Bottom 2.54: F4.1 100.96,57.62 102.23,56.35 Q12.D
N$29
  Bottom 0.406: IC5.3 287.65,94.45 286.38,95.72 286.38,107.15 282.57,110.96 282.57,117.31 281.3,118.58 IC6.8
N$30
  Bottom 0.406: Q12.G 96.39,61.94 C9.2 R17.1
N$31
  Bottom 0.406: R17.2 R18.1 Q13.1 Q14.1
N$32
  Bottom 0.406: 92.07,76.67 93.34,75.4 R18.2 89.53,70.32 86.99,67.78 C10.1 | 92.07,76.67 Q13.2 | IC1.7 85.72,91.91 92.7,84.92 Q14.2 92.07,76.67
N$33
  Bottom 0.406: C10.2 R19.1 84.45,55.08 80.64,58.89 80.64,89.37 83.18,91.91 IC1.6
N$34
  Bottom 0.254: R66.2 R35.1
  Bottom 0.406: R31.2 R32.2 235.58,133.82 | 235.58,133.82 R33.2 R34.2 231.77,127.47 230.5,126.2 R35.1 | IC7.2 243.2,132.55 241.93,133.82 235.58,133.82
N$35
  Bottom 0.254: R66.1 R65.2
N$36
  Bottom 0.406: IC7.1 R35.2 R36.1
N$37
  Bottom 0.406: IC3.6 243.2,104.61 244.47,105.88 R26.2 R27.2
N$38  (via drill 0.6)
  Top 0.254: R26.1 230.5,105.88 227.96,108.42 v227.96,117.31 | v227.96,141.44 226.69,142.71 224.15,142.71 219.07,147.79 R30.1
  Bottom 0.254: v227.96,117.31 v227.96,141.44
  Bottom 0.406: R26.1 IC3.7
N$39
  Bottom 0.406: R36.2 254.63,122.39 253.36,123.66 IC7.6 252.09,131.28 252.09,141.44 253.36,142.71 R37.1
N$40  (via drill 0.6)
  Top 0.254: v172.08,173.19 172.08,14.44 | 172.08,14.44 172.08,10.63 | v192.4,173.19 207.64,173.19 208.91,174.46 IC9.2 | S1.3 171.88,14.24 172.08,14.44
  Top 0.406: R45.1 173.35,9.36 172.08,10.63
  Bottom 0.254: v172.08,173.19 v192.4,173.19
N$41
  Bottom 0.406: R38.1 R37.2 267.33,135.09 266.06,133.82 257.17,133.82 255.9,132.55 IC7.7
N$42
  Top 0.254: R38.2 256.84,146.19
  Bottom 0.406: IC7.12 245.74,142.71 249.55,146.52 R38.2
N$44
  Bottom 0.254: R40.1 R39.1 238.12,145.25 243.2,140.17 IC7.13
N$45
  Bottom 0.254: R41.2 226.69,151.6 227.96,150.33 227.96,146.52 226.69,145.25 R39.2 227.96,142.71 236.85,142.71 240.66,138.9 IC7.14
N$46
  Bottom 0.406: SV3.2 R43.2
N$47
  Top 0.254: IC9.37 213.99,193.51 212.72,194.78 155.57,194.78 145.41,184.62 145.41,46.19 135.25,36.03 126.36,27.14 C28.1
  Bottom 0.406: C28.1 R43.1
N$48  (via drill 0.6)
  Top 0.254: v158.11,175.73 158.11,15.71 156.64,14.24 S2.3 | v193.67,175.73 IC9.1 | R46.1 144.14,9.36 145.41,10.63 S2.3 | S2.3 145.41,14.44
  Bottom 0.254: v158.11,175.73 v193.67,175.73
N$49
  Bottom 0.254: IC9.12 234.31,170.65 233.04,169.38 Q16.2 233.17,164.43 C26.1
N$50
  Bottom 0.254: IC9.13 236.85,170.65 238.12,169.38 Q16.1 237.99,164.43 C25.1
N$51
  Bottom 0.813: D8.A 98.42,180.81 SV4.3 | SV4.3 SV4.2 | Q17.D 102.23,164.3 103.5,165.57 103.5,178.27 102.23,179.54 SV4.3
N$52
  Top 0.254: C27.1 SV1.5
  Bottom 0.254: IC9.9 226.69,179.54 225.42,180.81 208.91,180.81 207.64,179.54 207.64,170.65 206.37,169.38 C27.1
N$53
  Bottom 0.254: SV2.5 216.53,160.49 215.26,159.22 211.45,159.22 210.18,160.49 210.18,164.3 211.45,165.57 IC9.3
N$54
  Top 0.254: IC9.17 247.01,180.81 188.59,180.81 187.32,179.54 187.32,30.95 189.86,28.41 206.37,28.41 215.26,19.52 R63.1
N$55  (via drill 0.6)
  Top 0.254: IC9.26 241.93,187.16 v153.03,187.16
  Bottom 0.254: Q17.G 104.77,161.76 R51.2 113.66,163.03 114.93,164.3 114.93,183.35 118.74,187.16 v153.03,187.16
N$56
  Bottom 0.406: LED1.K R47.1
N$57
  Top 0.254: IC9.21 254.63,187.16 253.36,185.89 179.7,185.89 174.62,180.81 174.62,24.6 179.7,19.52
  Top 0.406: 179.7,19.52 R47.2
N$58
  Top 0.254: IC9.20 254.63,183.35 253.36,184.62 183.51,184.62 178.43,179.54 178.43,27.14 186.05,19.52 R48.2
N$59
  Bottom 0.406: LED2.K R48.1
N$60
  Top 0.254: IC9.19 252.09,182.08 250.82,183.35 184.78,183.35 182.24,180.81 182.24,28.41 188.59,22.06 198.75,22.06 R49.2
N$61
  Bottom 0.406: LED3.K R49.1
N$62
  Top 0.254: IC9.18 249.55,182.08 186.05,182.08 184.78,180.81 184.78,84.29 184.78,29.68 189.86,24.6 206.37,24.6 R50.2
N$63
  Bottom 0.406: LED4.K R50.1
N$64
  Bottom 0.254: R52.2 Q19.C
N$65
  Top 0.254: M2.6 295.27,196.05 292.73,198.59 266.06,198.59 264.79,197.32 264.79,193.51 R56.2 | R56.2 266.06,190.97 263.52,188.43 R57.2 263.52,177 OK4.8 OK4.7 | R56.2 267.33,187.16 268.6,185.89 Q19.E 271.14,183.35 271.14,179.54 272.41,178.27 C34.2
N$66
  Bottom 0.254: OK3.2 R52.1
N$67
  Bottom 0.254: OK4.6 269.87,180.81 271.14,182.08 R57.1 276.22,179.54 281.3,179.54 282.57,180.81 M2.3
N$68
  Bottom 0.254: R53.2 271.14,196.05 273.68,193.51 274.95,193.51 R56.1 276.22,189.7 Q19.B
N$69
  Bottom 0.254: M2.4 297.81,188.43 299.08,189.7 299.08,194.78 297.81,196.05 R53.1
N$70
  Bottom 0.254: M2.2 M2.1
N$71
  Bottom 0.254: M2.5 288.92,190.97 286.38,188.43 OK3.3 286.38,177 285.11,178.27 C34.1 280.03,177 278.76,175.73 OK4.5
N$72
  Bottom 0.254: R59.2 Q18.B
  Bottom 0.406: Q18.B 295.27,159.22 296.54,157.95 R58.1
N$73
  Bottom 0.254: R55.2 OK4.2
N$74
  Bottom 0.254: R55.1 276.22,163.03 274.95,161.76 274.95,157.95 276.22,156.68 Q18.C
N$75
  Bottom 0.813: X2.1 17.1,105.92 17.14,105.88 | 17.14,105.88 19.68,103.34 19.68,98.26 20.95,96.99 F6.1 | F5.1 19.86,108.6 17.14,105.88
N$76
  Bottom 0.813: F5.2 42.36,132.73 37.46,137.63 24.76,137.63 22.22,140.17 22.22,164.3 TR2.1 13.33,173.19
N$77
  Bottom 0.813: TR3.1 25.83,66.31 42.54,83.02 42.54,96.99 F6.2
N$78
  Bottom 0.813: TR3.6 5.51,41.31 4.44,42.38 4.44,109.69 5.71,110.96 | X2.2 12.06,110.96 5.71,110.96 | TR2.6 7.18,147.99 4.44,145.25 4.44,112.23 5.71,110.96
N$79
  Bottom 0.813: TR2.11 51.56,167.98 52.7,166.84 B1.AC1
N$80
  Bottom 0.813: TR2.8 43.68,153 47.62,149.06 B1.AC2
N$81
  Bottom 0.813: R60.1 LED5.A
N$82
  Top 0.406: C41.1 78.23,167.98 79.37,166.84 79.37,147.79 78.1,146.52 C35.+
  Bottom 0.813: C35.+ 70.48,149.06 B1.+ 57.78,149.06 56.51,150.33 56.51,165.57 57.78,166.84 IC10.IN
N$83
  Bottom 0.406: LED6.A R61.1
N$84
  Bottom 0.813: R62.2 LED7.K
N$85
  Bottom 0.406: LED8.K R63.2
N$86
  Bottom 0.813: TR3.12 47.82,66.31 52.7,61.43 B2.AC1
N$87
  Bottom 0.813: TR3.7 47.82,41.31 52.7,46.19 B2.AC2
N$88
  Top 0.813: C43.1 66.54,32.35 C36.+
  Bottom 0.813: B2.+ 60.32,38.57 C36.+ 55.24,25.87 55.24,11.9 56.51,10.63 IC11.IN
N$90
  Top 0.813: C45.2 62.99,72.73 C37.-
  Bottom 0.813: B2.- 60.32,65.24 C37.- 65.4,86.83 61.59,90.64 IC12.IN
ON  (via drill 0.6)
  Top 0.254: 296.54,81.75 297.81,83.02 297.81,137.63 281.3,154.14 269.87,154.14 264.79,159.22 264.79,163.03 263.52,164.3 244.47,164.3 v241.93,166.84
  Top 0.406: R3.2 296.54,81.75
  Bottom 0.254: v241.93,166.84 241.93,171.92 240.66,173.19 240.66,187.16 239.39,188.43 IC9.27
  Bottom 0.406: Q1.G R3.2
RXD  (via drill 0.6)
  Top 0.254: v286.38,170.65 285.11,171.92 240.66,171.92 239.39,173.19 IC9.14
  Bottom 0.254: R54.1 287.65,171.92 v286.38,170.65 OK3.6
SCK  (via drill 0.6)
  Top 0.254: v263.52,161.76 249.55,161.76 248.28,160.49 230.5,160.49 v229.23,161.76
  Bottom 0.254: SV2.4 213.99,164.3 215.26,165.57 215.26,168.11 SV1.3 217.8,168.11 220.34,168.11 224.15,171.92 | 224.15,171.92 IC9.8 | IC6.3 286.38,110.96 287.65,109.69 296.54,109.69 299.08,112.23 299.08,135.09 283.84,150.33 283.84,151.6 282.57,152.87 276.22,152.87 272.41,156.68 272.41,159.22 271.14,160.49 264.79,160.49 v263.52,161.76 | v229.23,161.76 229.23,166.84 224.15,171.92
TXD
  Bottom 0.254: R59.1 260.98,159.22 258.44,161.76 258.44,180.81 243.2,180.81 241.93,179.54 IC9.15
U+  (1 unrouted)
  Top 3.81: RL1.P@ 235.05,44.18 234.31,44.92 234.31,75.4 231.77,77.94 203.83,77.94 F1.2
  Bottom 2.54: 100.96,80.48 F3.2 202.38,111.14 203.83,109.69 F2.2 | 100.96,80.48 F4.2 | F1.2 103.68,77.76 100.96,80.48
  Bottom 3.81: 203.83,109.69 203.83,77.94
UIST  (2 unrouted)
  Bottom 0.406: R20.1 231.77,86.83 227.96,83.02 227.96,60.16 233.04,55.08 253.36,55.08 255.9,52.54 255.9,39.84 254.63,38.57 247.01,38.57
  Bottom 3.81: JP3.1 227.96,30.95 235.58,38.57 239.39,38.57 | RL1.S 246.4,39.18 247.01,38.57
UIST_ADC  (via drill 0.6)
  Top 0.406: C18.1 R30.2
  Bottom 0.254: 200.02,156.68 198.75,157.95 198.75,188.43 201.29,190.97 IC9.40
  Bottom 0.406: 200.02,156.68 C18.1
  other vias: 208.91,156.68
VREF
  Top 0.406: R24.2 286.38,131.28 | 286.38,131.28 C13.2 | 286.38,131.28 VR1.C
  Bottom 0.254: R65.3 268.6,119.85 272.41,123.66 272.41,130.01 273.68,131.28 R24.2
  Bottom 0.406: IC6.6 VR1.C VR1.R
